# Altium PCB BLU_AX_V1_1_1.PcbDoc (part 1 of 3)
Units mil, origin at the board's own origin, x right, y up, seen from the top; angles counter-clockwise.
Board outline 2623.2 x 4215 mil, 6 copper layers (Top Layer, GND1, PWR, Signal Inner, GND2, Bottom Layer), stack 76.535 mil thick; 238 components, 119 nets, 699 pads, 786 vias.
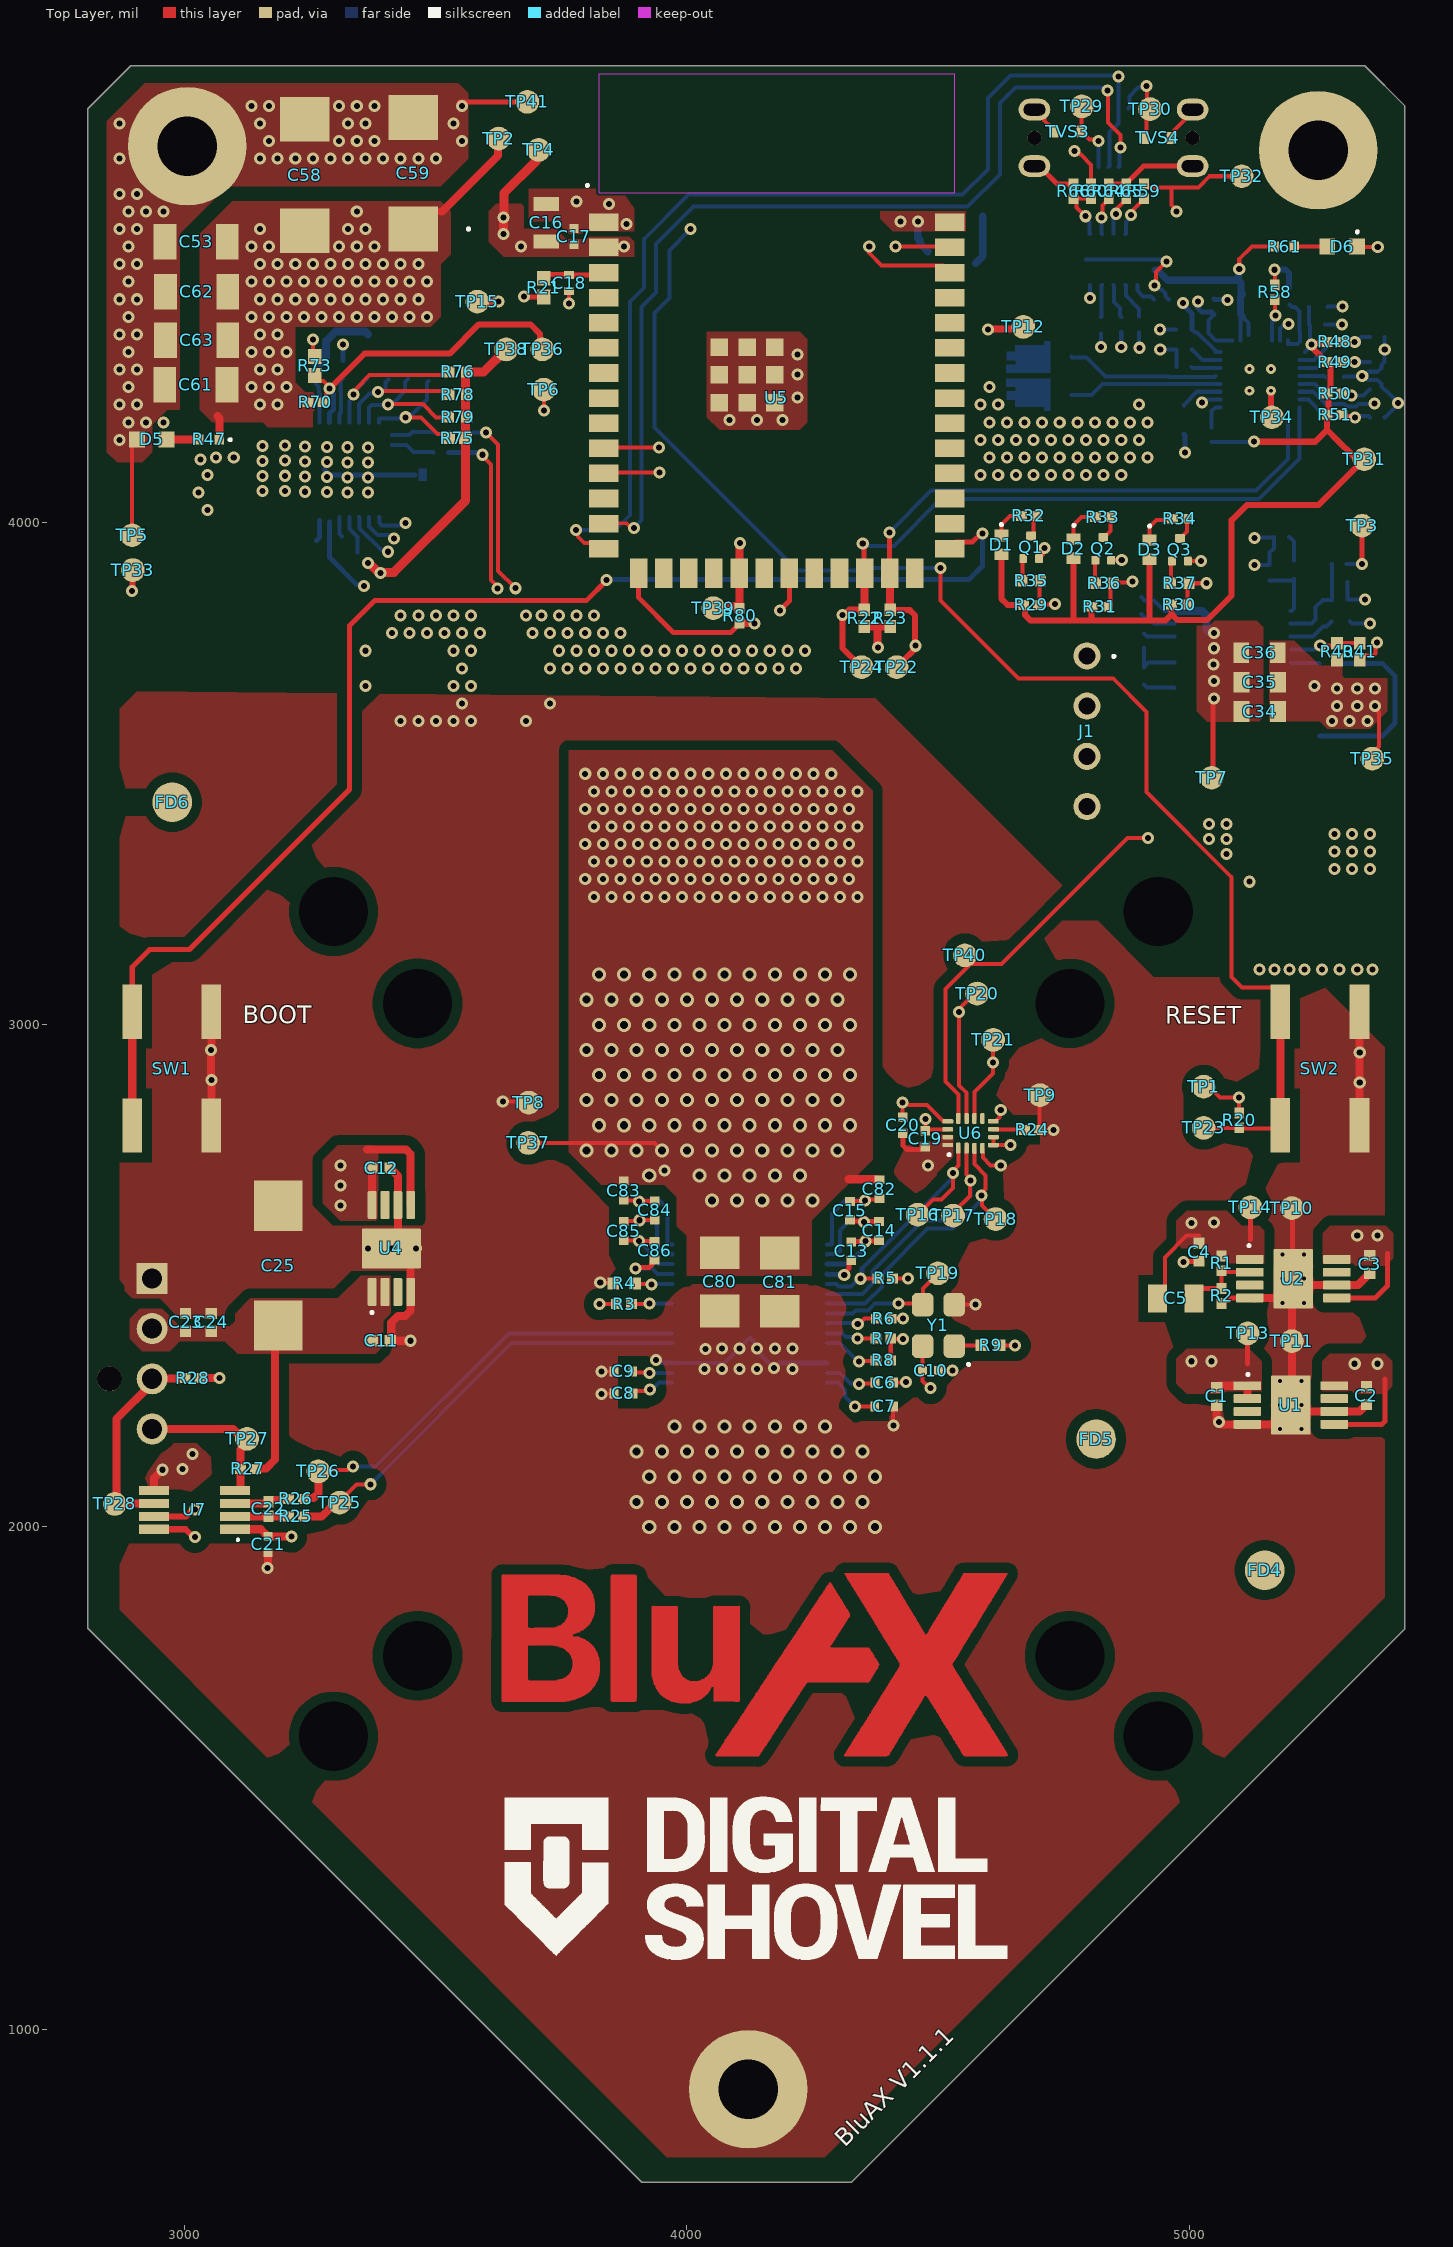
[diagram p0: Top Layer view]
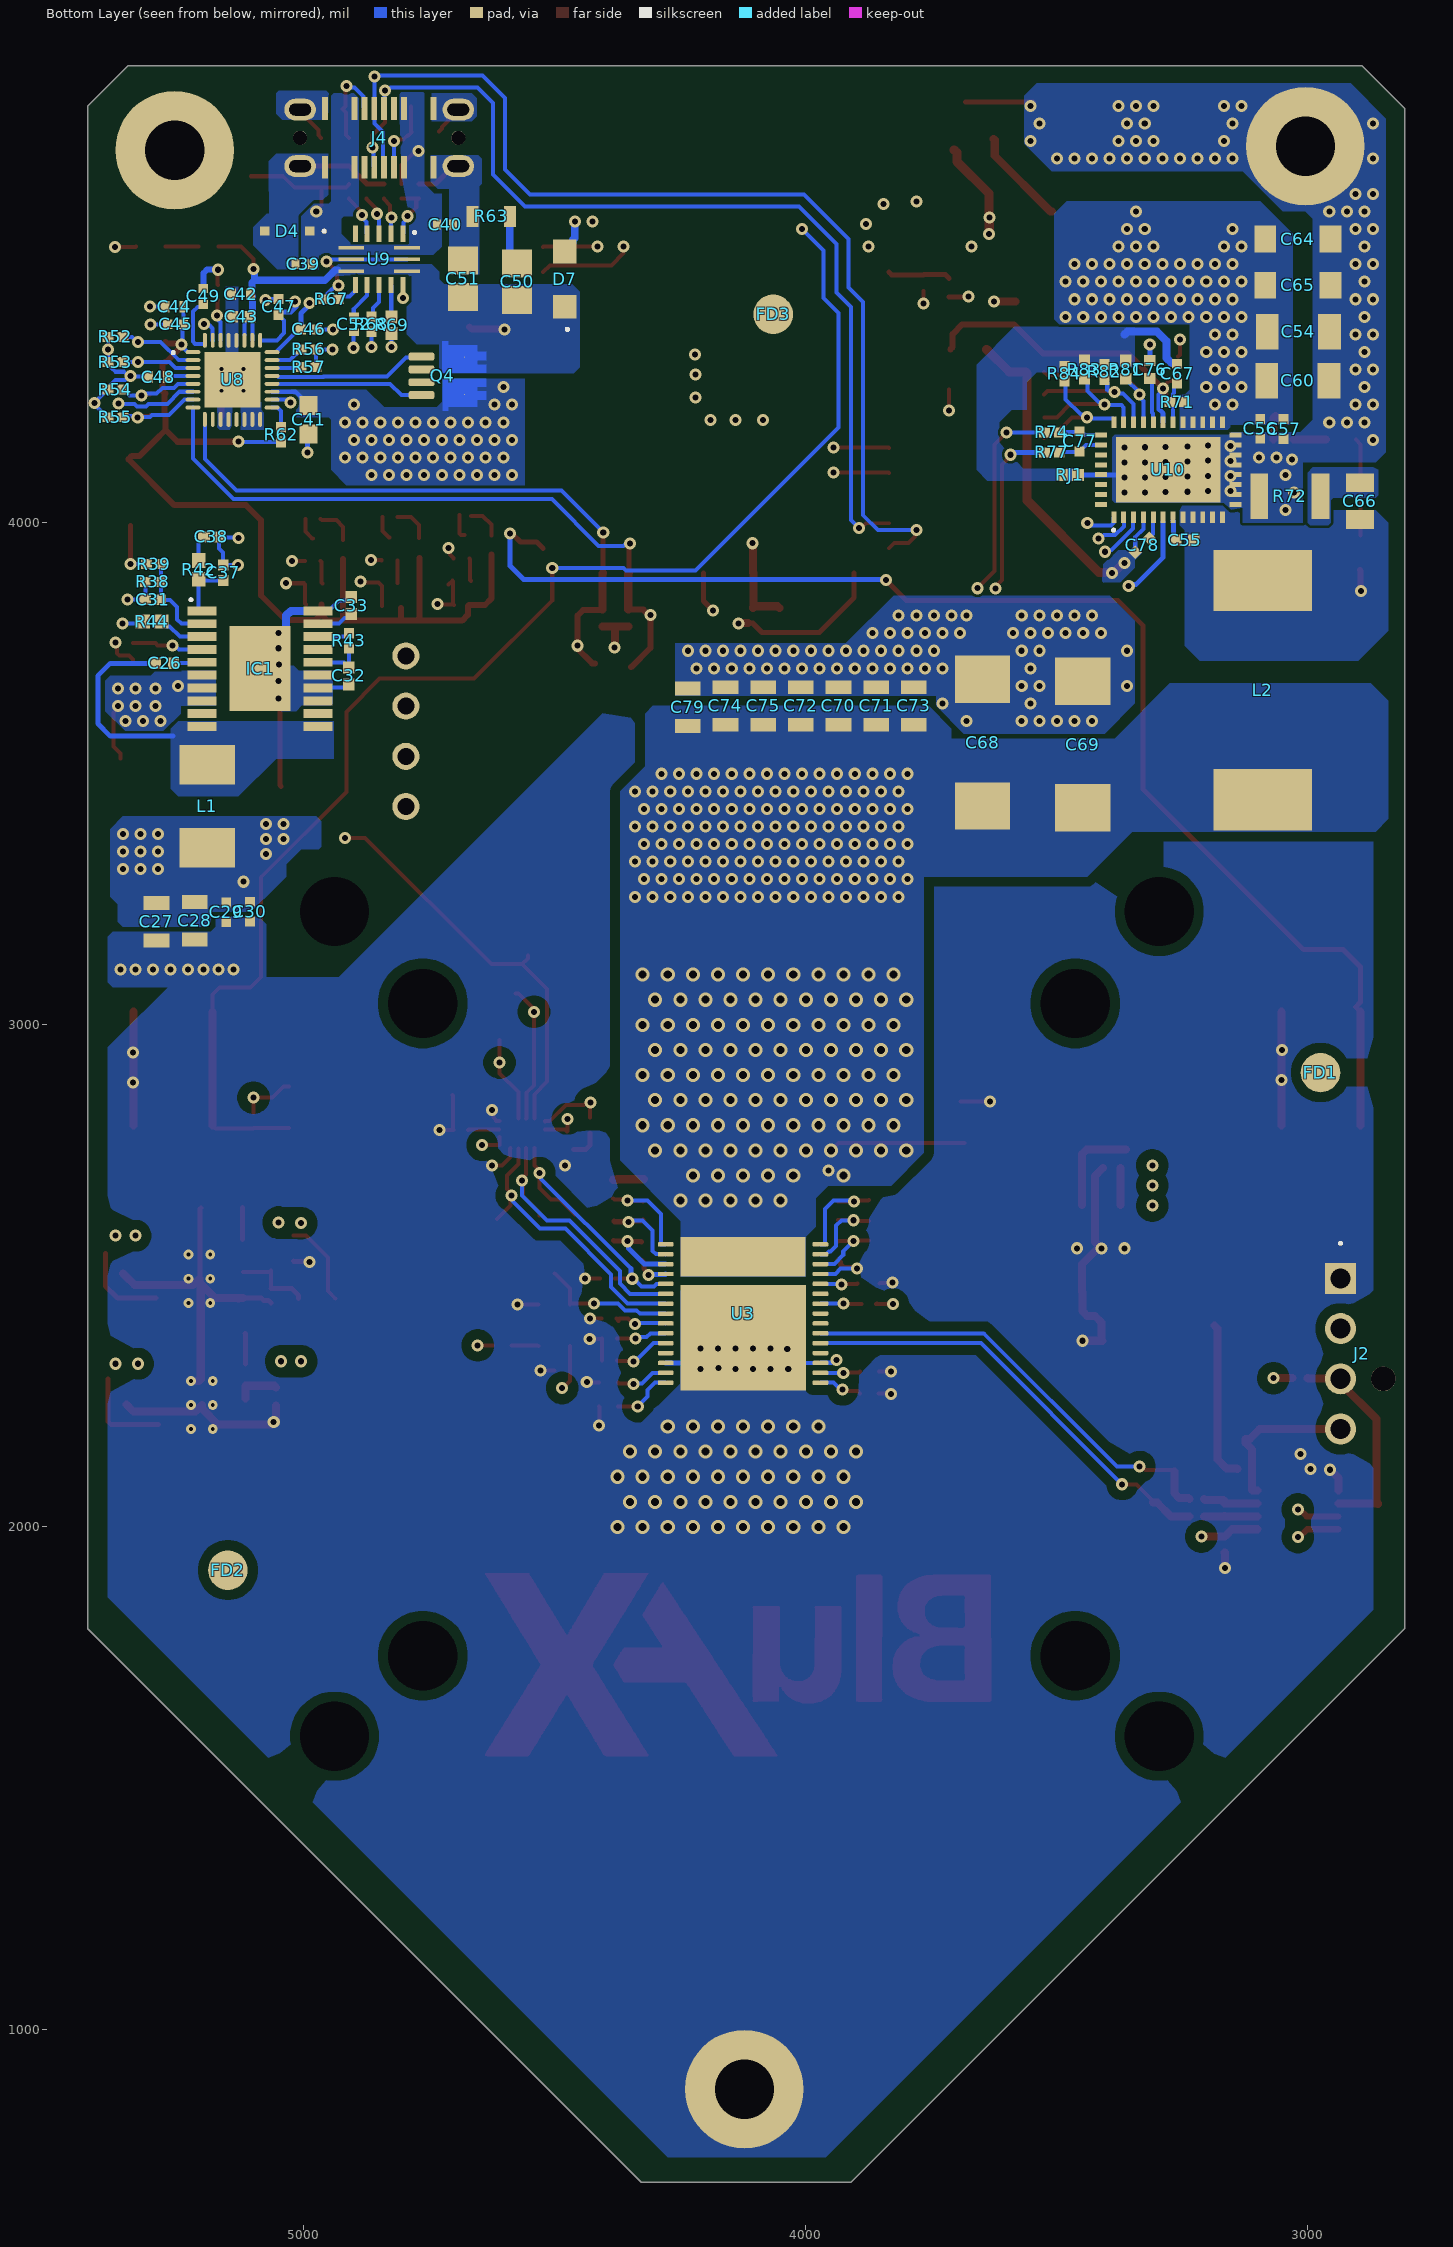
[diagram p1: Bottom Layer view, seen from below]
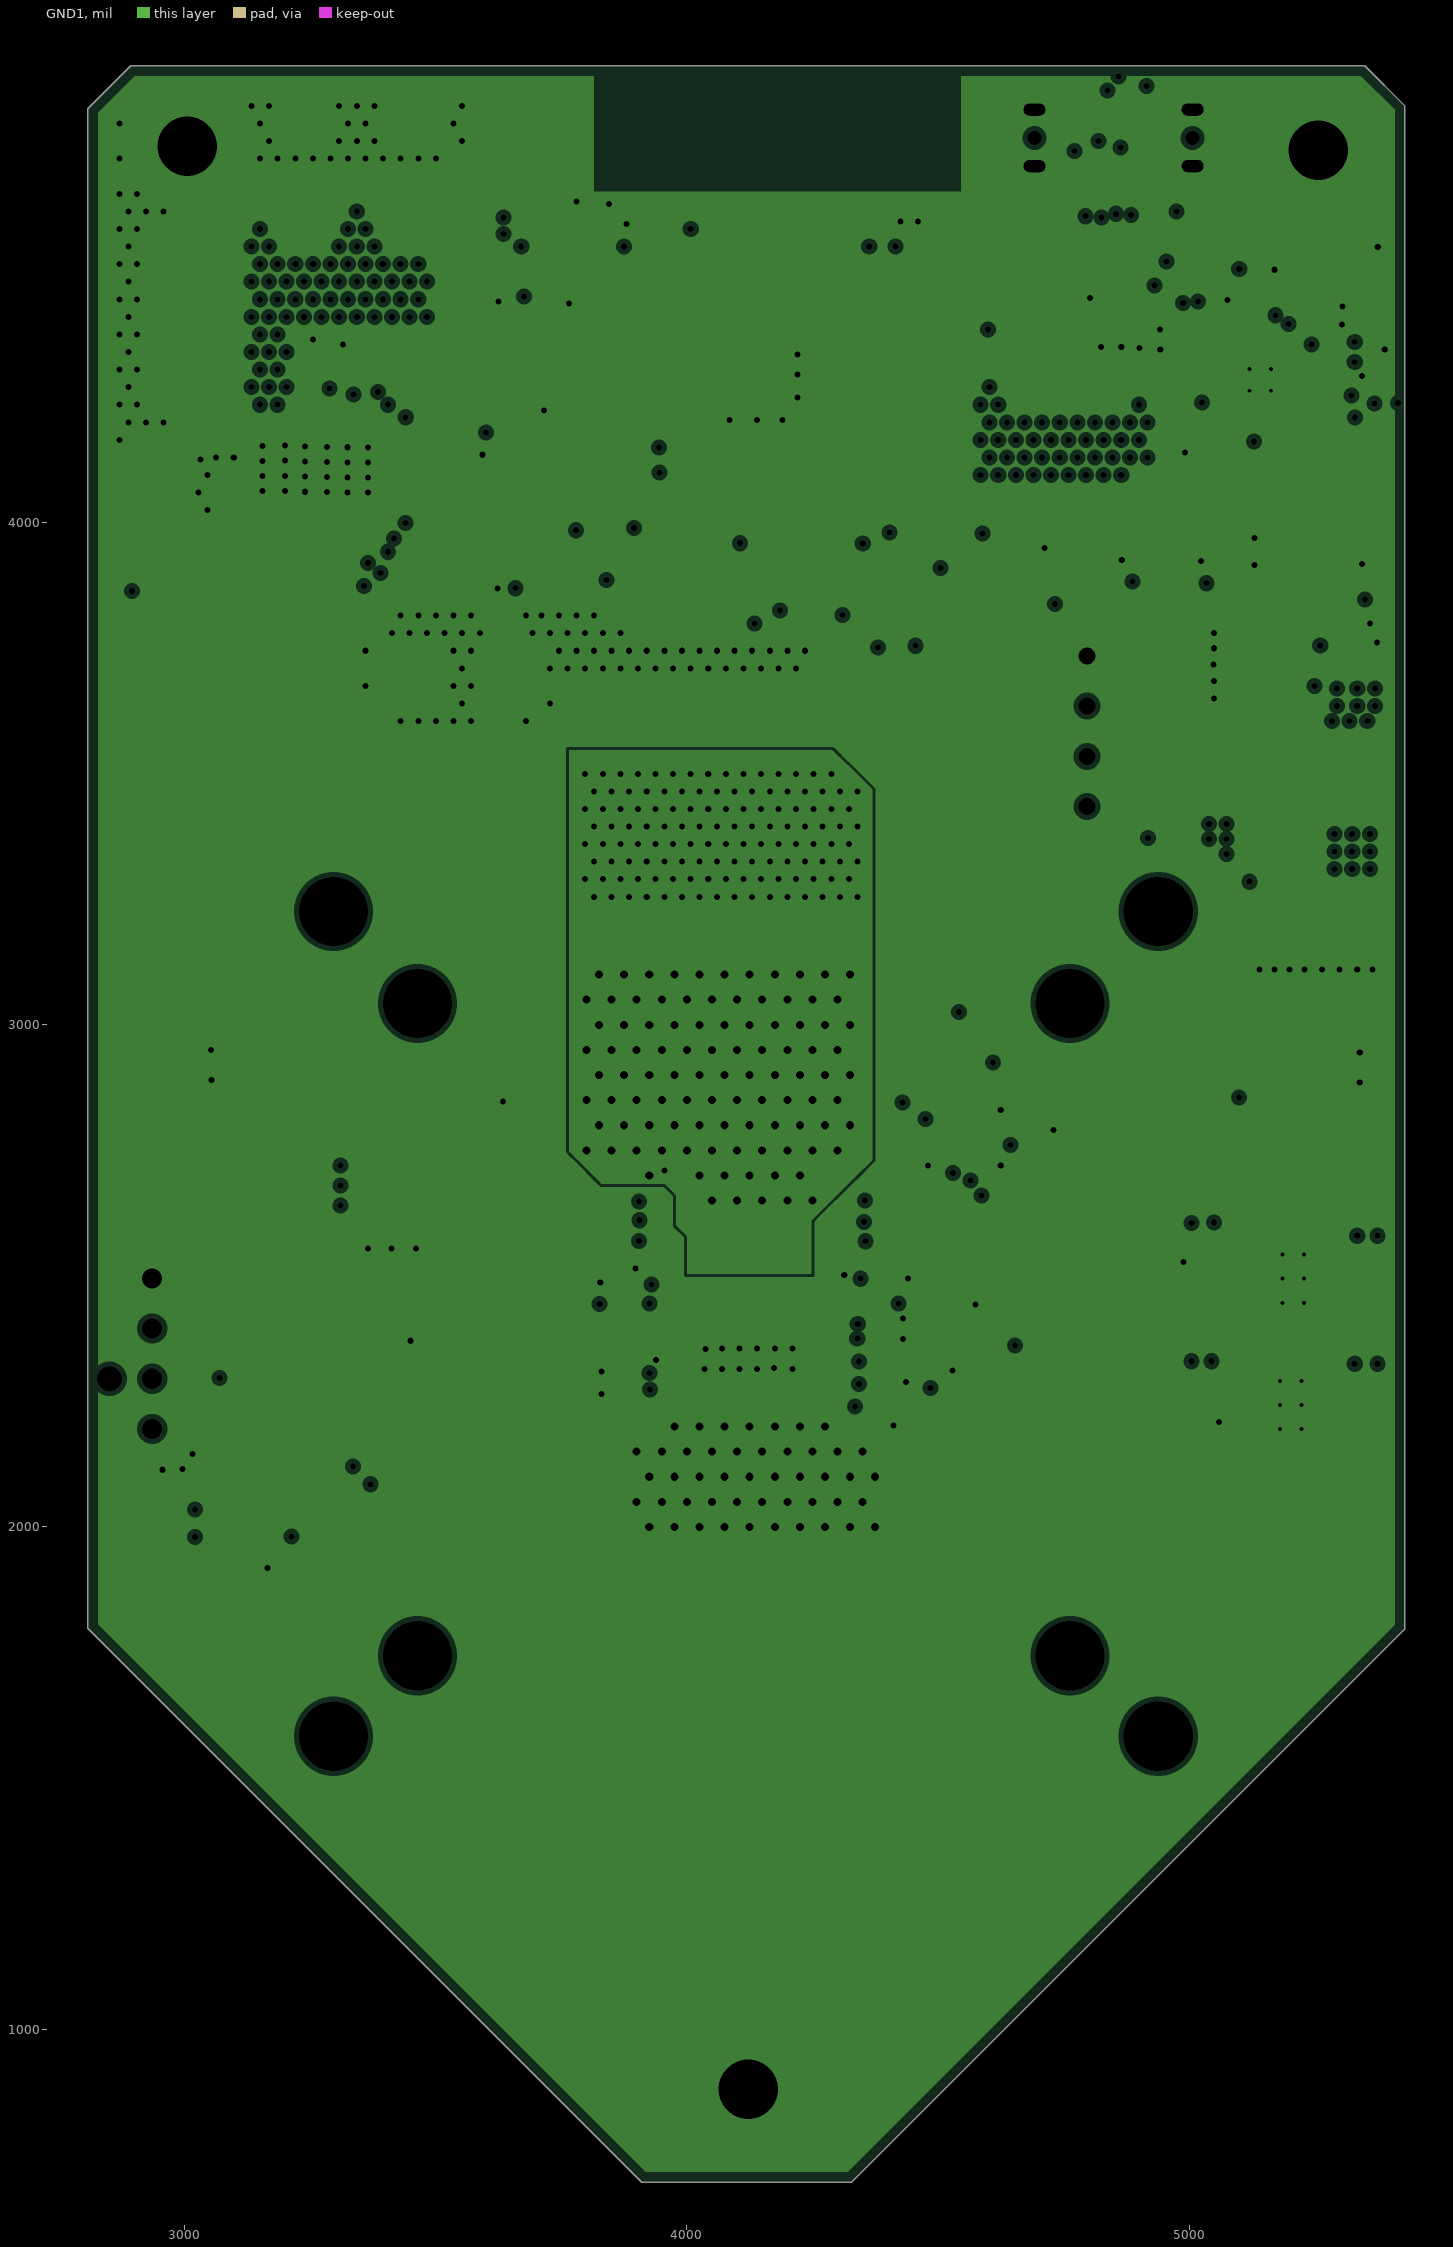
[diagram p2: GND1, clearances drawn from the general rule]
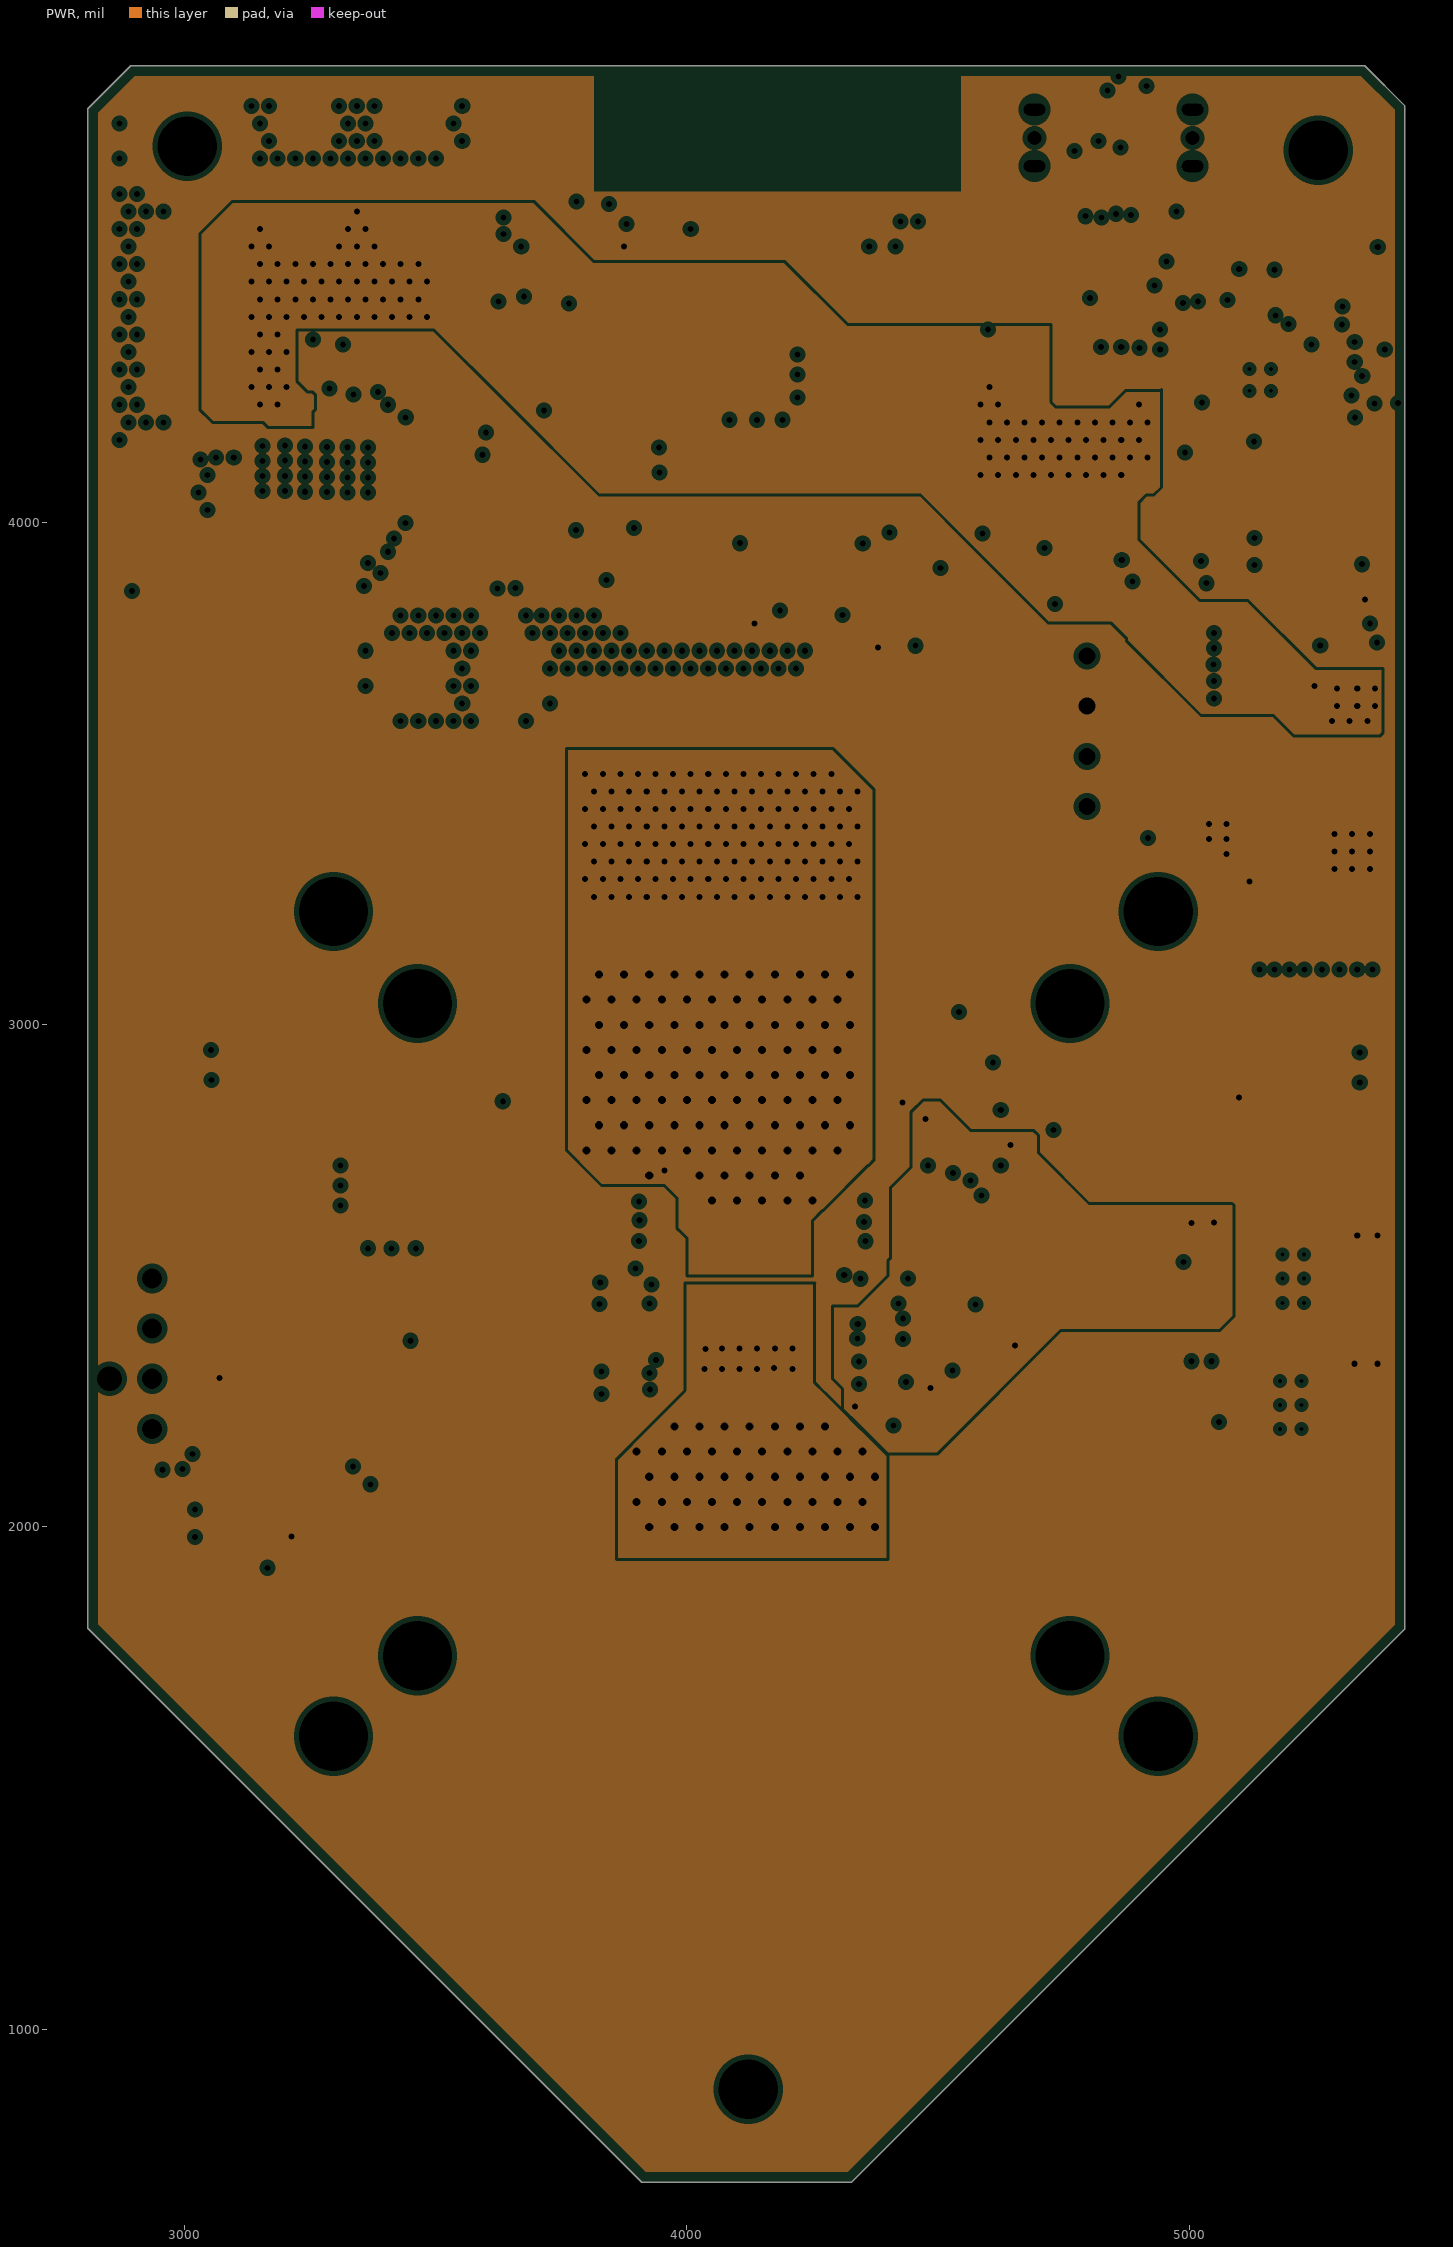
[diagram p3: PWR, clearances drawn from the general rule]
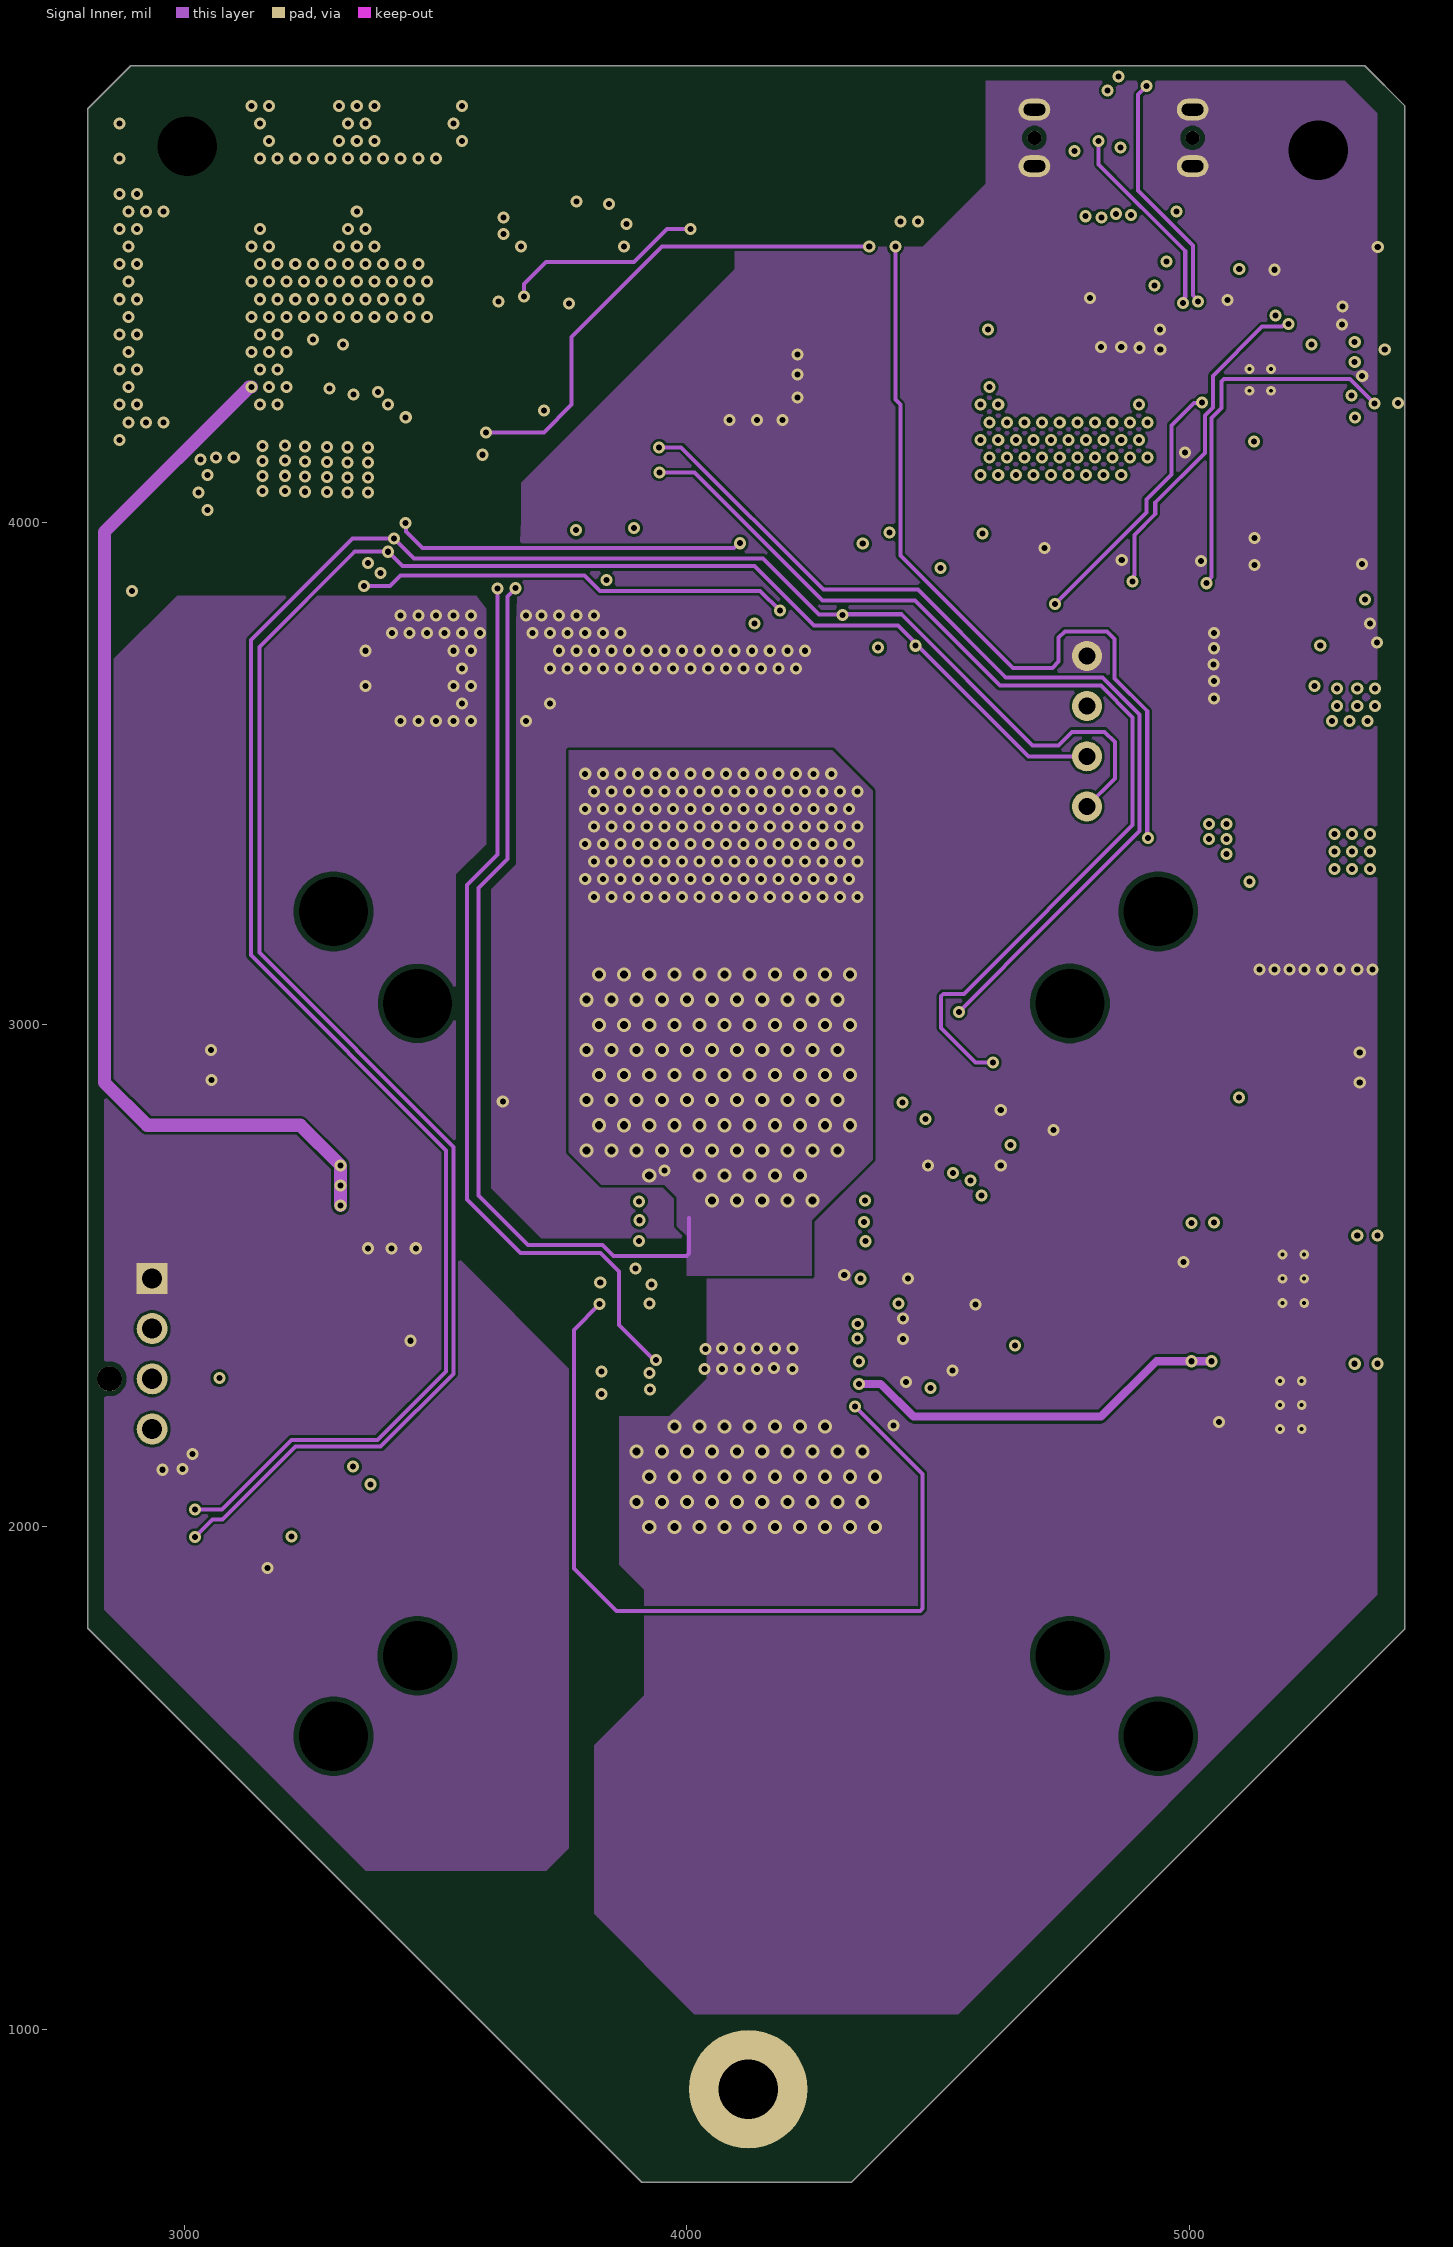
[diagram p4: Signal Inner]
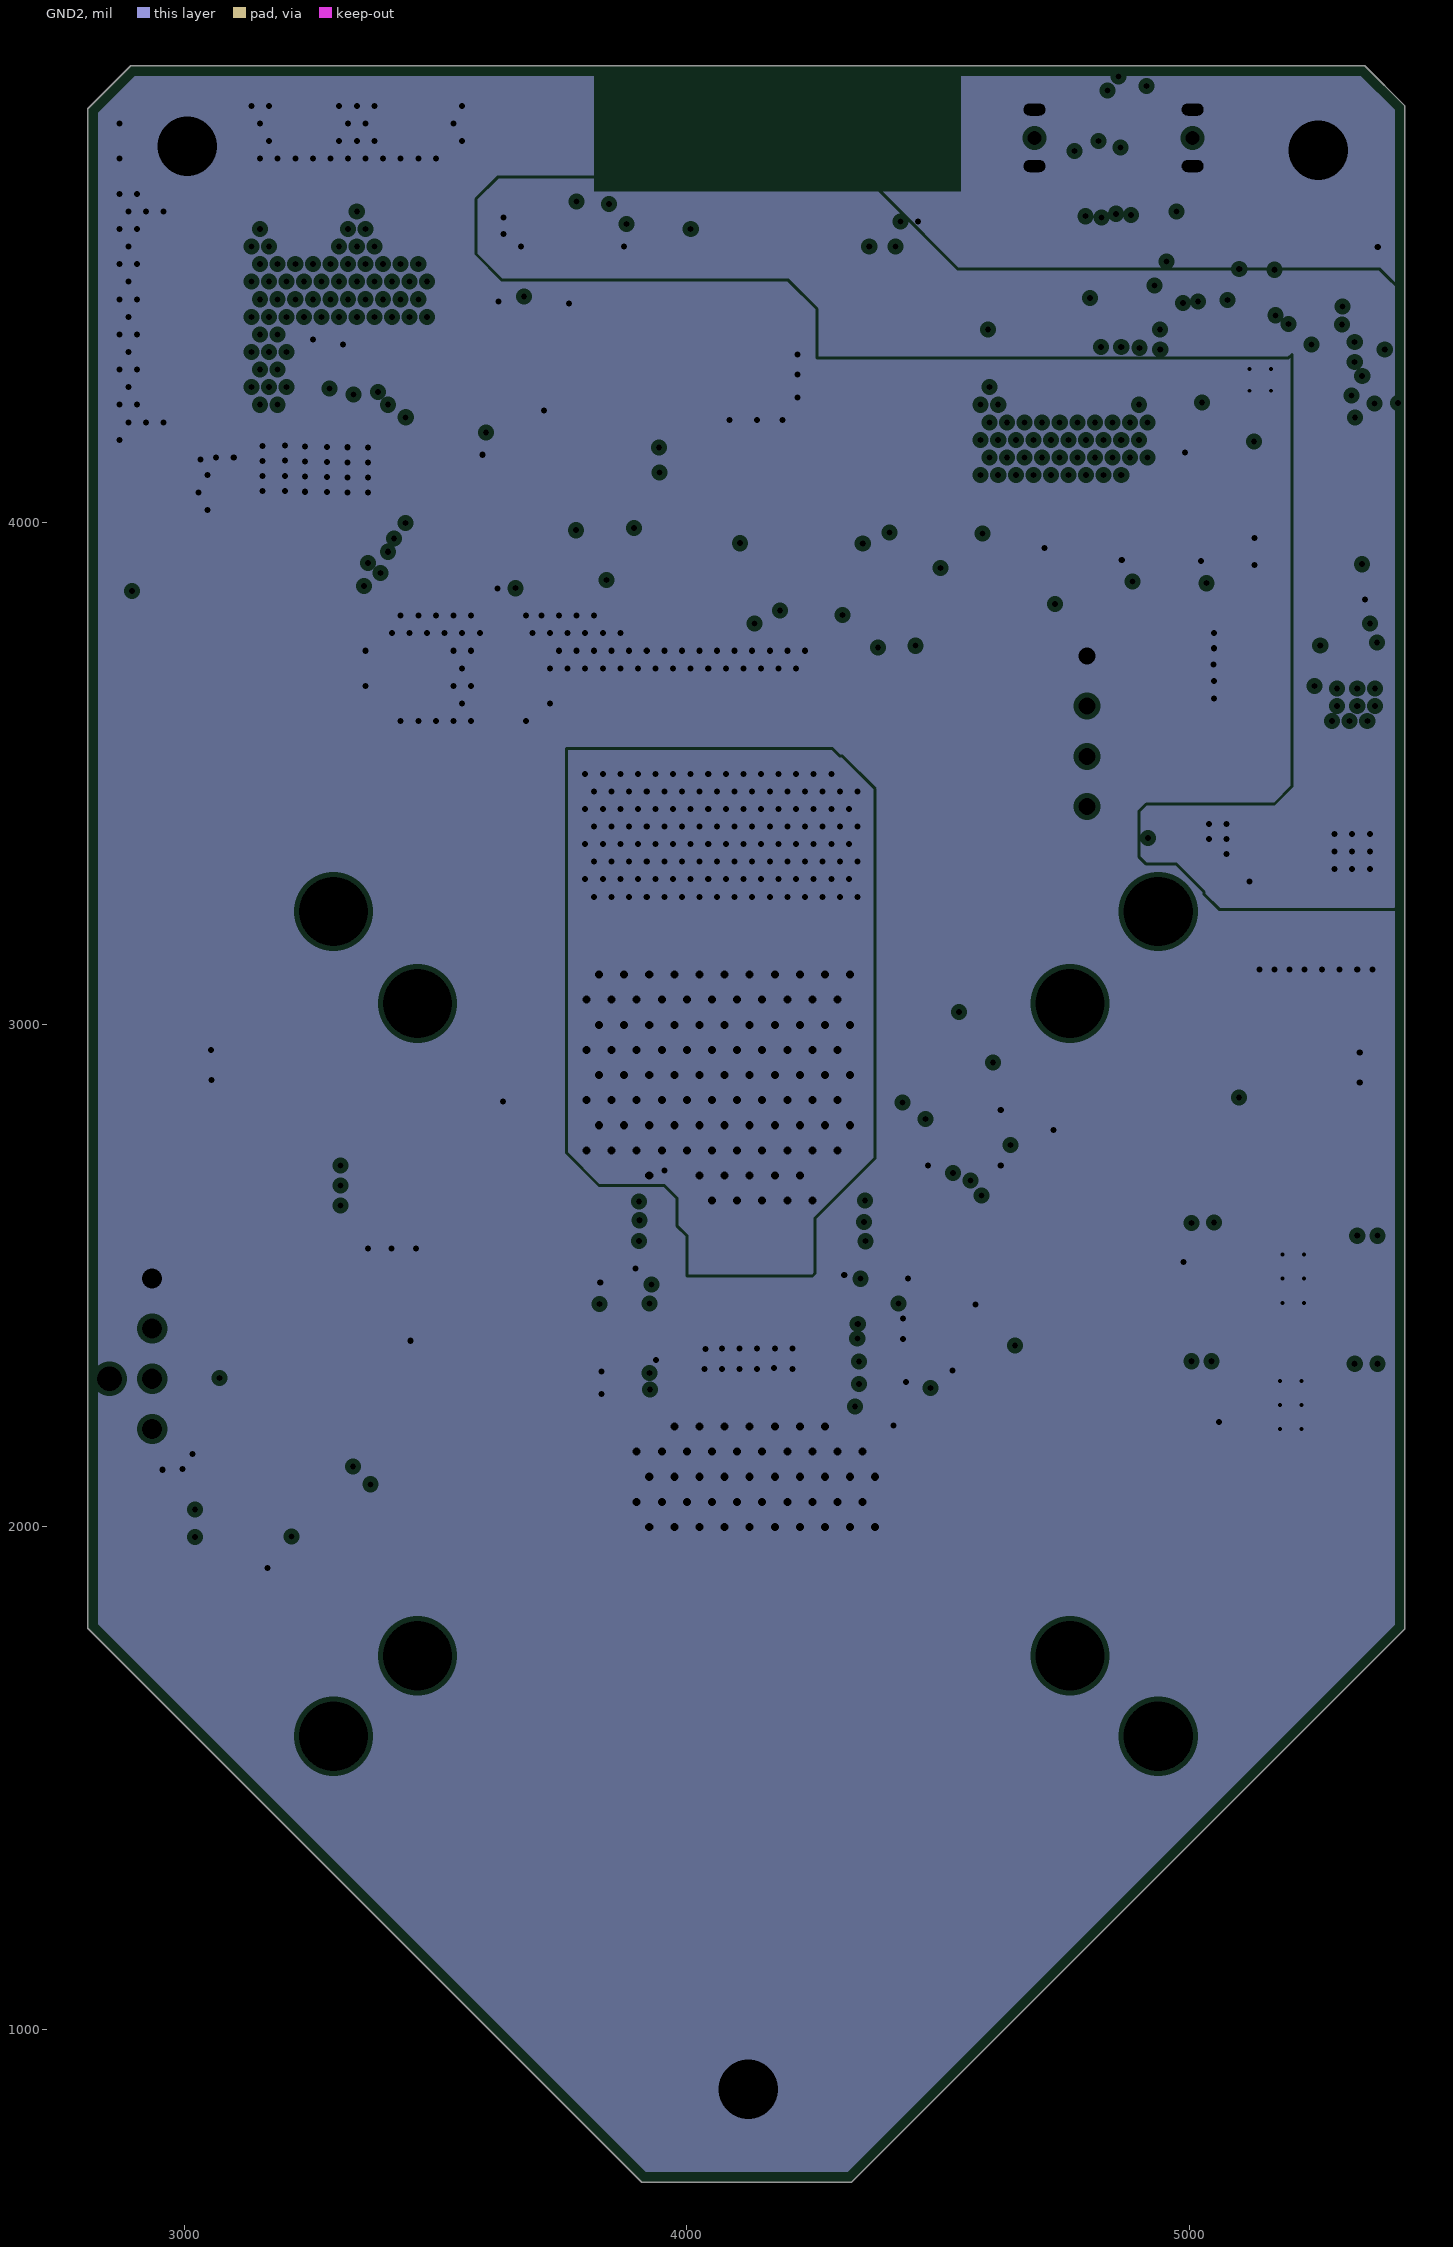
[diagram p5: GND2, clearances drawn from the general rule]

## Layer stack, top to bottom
Top Solder: solder mask 0.4, Solder Resist, Dk 3.5
Top Layer: signal copper 0.689
Dielectric 1: prepreg 4.055, PP-015, Dk 4.45
GND1: plane copper 1.378, net (Multiple Nets)
Dielectric 2: core 28.74, Core-010, Dk 4.6
PWR: plane copper 1.378, net (Multiple Nets)
Dielectric 3: prepreg 4.055, PP-015, Dk 4.45
Signal Inner: signal copper 1.378
Dielectric 4: core 28.74, Core-010, Dk 4.6
GND2: plane copper 1.378, net (Multiple Nets)
Dielectric 5: prepreg 4.055, PP-015, Dk 4.45
Bottom Layer: signal copper 0.689
Bottom Solder: solder mask 0.4, Solder Resist, Dk 3.5

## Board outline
2806.8,1798.2 3910,695 4327.89,695 5430,1797.11 5430,4830 5350,4910 2892.37,4910 2807.63,4825.26 2806.8,4825.26

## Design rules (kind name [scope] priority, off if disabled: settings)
Clearance Clearance_3 [InNamedPolygon('signal pour')] p1: gap=20 ignorepadtopadclearanceinfootprint=FALSE
Clearance Clearance_1 [InNamedPolygon('pour')] p2: gap=20 ignorepadtopadclearanceinfootprint=FALSE
Clearance Clearance_2 [InNamedPolygon('pour')] p3 off: gap=20 ignorepadtopadclearanceinfootprint=FALSE
Clearance [All] p4: gap=5.5 ignorepadtopadclearanceinfootprint=FALSE except(10: Arc-Hole Track-Hole SMDPad-Hole THPad-Hole Via-Hole Fill-Hole Poly-Hole Region-Hole Text-Hole)
DiffPairsRouting [InDifferentialPairClass('USB90_DIFF')] p1: maxlimit=15.88 minlimit=5.5 mostfreqgap=15.88 toplayer_mingap=15.88 toplayer_prefgap=15.88 toplayer_minwidth=7.49 toplayer_maxwidth=7.49 toplayer_prefwidth=7.49 midlayer1_maxgap=5.5 midlayer1_prefgap=5.5 midlayer1_minwidth=8 midlayer1_maxwidth=8 midlayer1_prefwidth=8 bottomlayer_mingap=15.88 bottomlayer_maxgap=15.88 bottomlayer_minwidth=7.94 bottomlayer_maxwidth=7.94 bottomlayer_prefwidth=7.94 impedanceprofiledriven=TRUE impedanceprofileid={67CD1C7F-876C-4BAD-9804-FA39EDEF8C0B} impedanceprofilevalue=90.000000 maxuncoupledlength=500
HoleSize [All] p1: absolutevalues=TRUE maxlimit=500 minlimit=1 maxpercent=80.000 minpercent=20.000
MinimumSolderMaskSliver [All] p1: minsoldermaskwidth=3.5
PlaneClearance [All] p1: clearance=10
PlaneConnect [All] p1: planeconnectstyle=Direct reliefexpansion=20 reliefentries=4 reliefconductorwidth=10 reliefairgap=10
PolygonConnect [All] p1: connectstyle=Direct reliefconductorwidth=10 reliefentries=4 polygonreliefangle="90 Angle" airgapwidth=10
RoutingVias [All] p1: holewidth=28 width=50 viastyle="Through Hole" minholewidth=28 minwidth=50 maxholewidth=28 maxwidth=50
SilkToSolderMaskClearance [IsPad] p1: minsilkscreentomaskgap=3.5 clearancetoexposedcopper=TRUE
SolderMaskExpansion [All] p1: expansion=4 istentingtop=FALSE
Width [All] p1: maxlimit=45 minlimit=8 preferedwidth=10 minimp=50.000000 maximp=50.000000 favimp=50.000000
24 further rules are at their usual default settings.

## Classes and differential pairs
differential pair class USB90_DIFF: USB
component class 14: C11 C12 U4
net class PWR: 1V2 3V3_ESP 3V3_IN DGND FS NetC55_2 SW V_eFuse VBUS VCORE
component class Main: TP3 TP4 TP5 TP6 TP7 TP8 TP9 TP10 TP11 TP15 TP41
component class 13: C6 C7 C8 C9 C13 C14 C15 C80 C81 C82 C83 C84 C85 C86 R3 R4 R5 R6 R7 R8 TP16 TP17 TP18 TP19 U3
component class 12: C21 C22 C23 C24 C25 J2 R25 R26 R27 R28 TP25 TP26 TP27 TP28 U7
component class 11: C1 C2 C3 C4 C5 R1 R2 TP13 TP14 U1 U2
component class 10: J1
component class 9: D1 D2 D3 Q1 Q2 Q3 R29 R30 R31 R32 R33 R34 R35 R36 R37
component class 8: C16 C17 C18 C19 C20 R20 R21 R22 R23 R24 SW1 SW2 TP20 TP21 TP22 TP23 TP24 TP40 U5 U6
component class 7: FD1 FD2 FD3 FD4 FD5 FD6
component class 6: C10 R9 Y1
component class 4: C39 C40 C41 C42 C43 C44 C45 C46 C47 C48 C49 C50 C51 C52 D4 D5 D6 D7 J4 Q4 R47 R48 R49 R50 R51 R52 R53 R54 R55 R56 R57 R58 R59 R60 R61 R62 R63 R64 R65 R66 R67 R68 R69 TP12 TP29 TP30 TP31 TP32 TVS3 TVS4 U8 U9
component class 3: C53 C54 C55 C56 C57 C58 C59 C60 C61 C62 C63 C64 C65 C66 C67 C68 C69 C70 C71 C72 C73 C74 C75 C76 C77 C78 C79 L2 R70 R71 R72 R73 R74 R75 R76 R77 R78 R79 R80 R81 R82 R83 R84 RJ1 TP33 TP34 TP35 TP36 TP37 TP38 TP39 U10
component class 2: C26 C27 C28 C29 C30 C31 C32 C33 C34 C35 C36 C37 C38 IC1 L1 R38 R39 R40 R41 R42 R43 R44 TP1 TP2
differential pair USB: +USB_P -USB_N

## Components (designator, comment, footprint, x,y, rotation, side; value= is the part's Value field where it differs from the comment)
C1 "CC0402KRX7R9BB104" FP-CC0402-IPC_B 5055,2260 r90 top value=100nF
C2 "CC0402KRX7R9BB104" FP-CC0402-IPC_B 5353.31,2261.63 r90 top value=100nF
C3 "CC0402KRX7R9BB104" FP-CC0402-IPC_B 5360,2522.8 r90 top value=100nF
C4 "CC0402KRX7R9BB104" FP-CC0402-IPC_B 5020,2547.2 r90 top value=100nF
C5 "CC0805KRX7R9BB102" FP-CC0805-0_85-MFG 4973.58,2455 r0 top value=1nF
C6 "EMK105BJ105KV-F" FP-0402-L_1_0_0_05-W_0_5-MFG#1 4393.1,2287.63 r0 top value=1uF
C7 "EMK105BJ105KV-F" FP-0402-L_1_0_0_05-W_0_5-MFG#1 4392.72,2240.19 r0 top value=1uF
C8 "EMK105BJ105KV-F" FP-0402-L_1_0_0_05-W_0_5-MFG#1 3873.57,2266.12 r180 top value=1uF
C9 "EMK105BJ105KV-F" FP-0402-L_1_0_0_05-W_0_5-MFG#1 3873.37,2309.84 r180 top value=1uF
C10 "CC0402KRX7R7BB104" FP-CC0402-IPC_C 4485.19,2311.47 r0 top value=0.1uF
C11 "CC0402KRX7R9BB104" FP-CC0402-IPC_B 3391.36,2370.81 r180 top value=100nF
C12 "CC0402KRX7R9BB104" FP-CC0402-IPC_B 3390.79,2714.79 r180 top value=100nF
C13 "EMK105BJ105KV-F" FP-0402-L_1_0_0_05-W_0_5-MFG#2 4327.32,2549.05 r90 top value=1uF
C14 "EMK105BJ105KV-F" FP-0402-L_1_0_0_05-W_0_5-MFG#2 4382.71,2589.42 r90 top value=1uF
C15 "EMK105BJ105KV-F" FP-0402-L_1_0_0_05-W_0_5-MFG#2 4324.57,2629.68 r90 top value=1uF
C16 "GRM21BR61E106KA73L" FP-GRM21B-0_15-MFG 3720,4597.4 r90 top value=10µF
C17 "CC0402KRX7R7BB104" FP-CC0402-IPC_C 3775,4570 r90 top value=0.1uF
C18 "GRM155R71C104KA88D" FP-GRM15-MFG 3765.21,4477.3 r90 top value=100nF
C19 "CC0402KRX7R7BB104" FP-CC0402-IPC_C 4474.73,2773.11 r90 top value=0.1uF
C20 "CC0402KRX7R7BB104" FP-CC0402-IPC_C 4430,2800 r270 top value=0.1uF
C21 "CC0402KRX7R7BB104" FP-CC0402-IPC_C 3165.74,1965.08 r270 top value=0.1uF
C22 "C0402C471K5RACTU" FP-0402-L_1_0_1-W_0_5_0_1-IPC_C 3166.4,2035.94 r270 top value=470pF
C23 "CC0402KRX7R9BB104" FP-CC0402-IPC_B 3001.53,2407.36 r270 top value=100nF
C24 "CC0402KRX7R9BB104" FP-CC0402-IPC_B 3052.65,2407.56 r270 top value=100nF
C25 "293D476X9016D2TE3" VISH-7343-31_N 3186.48,2520.38 r90 top value=47µF
C26 "CC0402KRX7R9BB104" FP-CC0402-IPC_B 5277.2,3720 r180 bottom value=100nF
C27 "GRM21BR71A106KA73L" FP-GRM21B-0_15-MFG 5293.18,3205.35 r270 bottom value=10uF
C28 "GRM21BR71A106KA73L" FP-GRM21B-0_15-MFG 5216.77,3207.15 r270 bottom value=10uF
C29 "CC0402KRX5R6BB105" FP-CC0402-MFG 5154.2,3224 r270 bottom value="1 uF"
C30 "CC0402KRX5R6BB105" FP-CC0402-MFG 5107.2,3225.41 r270 bottom value="1 uF"
C31 "GRM1555C1H221GA01J" CAPC1005X55X25LL05T10 5300.14,3846.72 r0 bottom value=220pF
C32 "GRM155R61E105KA12D" FP-GRM155-0_05-IPC_B 4910,3695 r270 bottom
C33 "GRM155R61E105KA12D" FP-GRM155-0_05-IPC_B 4905,3835 r90 bottom
C34 "C2012X7R1E335K125AB" FP-C2012-125-0_2-MFG 5140.78,3623.97 r180 top value=3.3uF
C35 "C2012X7R1E335K125AB" FP-C2012-125-0_2-MFG 5140.68,3682.23 r180 top value=3.3uF
C36 "C2012X7R1E335K125AB" FP-C2012-125-0_2-MFG 5140.3,3741.03 r180 top value=3.3uF
C37 "GRM1555C1H470GA01D" CAPC1005X55X25LL05T10 5160.4,3900.12 r270 bottom value=47pF
C38 "GRM1555C1H822JE01D" FP-GRM155-0_15-IPC_C 5183.96,3971.62 r180 bottom value=8.2nF
C39 "GRM155R71H223KA12D" FP-GRM155-0_05-MFG 5000.75,4515 r0 bottom value=22nF
C40 "GRM155R71H223KA12D" FP-GRM155-0_05-MFG 4718.4,4593.57 r180 bottom value=22nF
C41 "GCM188R71E105KA64J" FP-GCM188-0_1-IPC_B 4990,4205 r270 bottom value=1uF
C42 "GRM155R61A106ME11D" FP-GRM155-0_2-MFG 5125,4455 r0 bottom value=10uF
C43 "CC0402KRX7R9BB104" FP-CC0402-IPC_B 5124.37,4410.08 r0 bottom value=100nF
C44 "GRM155R61A106ME11D" FP-GRM155-0_2-MFG 5257.54,4430.09 r0 bottom value=10uF
C45 "CC0402KRX7R7BB104" FP-CC0402-IPC_C 5255,4395 r0 bottom value=0.1uF
C46 "C0402C331K5RACTU" FP-C0402-BB-MFG 4990,4385 r180 bottom value=330pF
C47 "C0402C331K5RACTU" FP-C0402-BB-MFG 5050,4430 r90 bottom value=330pF
C48 "GRM155R61A106ME11D" FP-GRM155-0_2-MFG 5290,4290 r0 bottom value=10uF
C49 "CC0402KRX7R7BB104" FP-CC0402-IPC_C 5200,4450.83 r90 bottom value=0.1uF
C50 "GRM21BR61H475KE51L" FP-GRM21B-0_15-IPC_A 4575,4480 r90 bottom value=4.7µF
C51 "GRM21BR61H475KE51L" FP-GRM21B-0_15-IPC_A 4682.79,4485.71 r90 bottom value=4.7µF
C52 "GRM155R71H223KA12D" FP-GRM155-0_05-MFG 4900,4395 r270 bottom value=22nF
C53 "GRM31CC81E226ME11L" FP-GRM31C-0_3-e0_3_0_8-MFG 3022.42,4559.69 r0 top
C54 "GRM31CC81E226ME11L" FP-GRM31C-0_3-e0_3_0_8-MFG 3019.24,4380.2 r0 bottom
C55 "CC0402KRX7R9BB104" FP-CC0402-IPC_B 3245,3965 r180 bottom value=100nF
C56 "CC0402KRX7R8BB222" FP-CC0402-MFG 3094.96,4186.93 r270 bottom value=2.2nF
C57 "CC0402KRX7R8BB222" FP-CC0402-MFG 3048.52,4186.54 r270 bottom value=2.2nF
C58 "593D107X9020E2TE3" 593D107X9020E2TE3-Footprint-1 3237.67,4694.89 r180 top
C59 "593D107X9020E2TE3" 593D107X9020E2TE3-Footprint-1 3453.81,4698.65 r180 top
C60 "GRM31CC81E226ME11L" FP-GRM31C-0_3-e0_3_0_8-MFG 3019.85,4282.63 r0 bottom
C61 "GRM31CC81E226ME11L" FP-GRM31C-0_3-e0_3_0_8-MFG 3022.01,4275 r0 top
C62 "GRM31CC81E226ME11L" FP-GRM31C-0_3-e0_3_0_8-MFG 3023.73,4459.68 r0 top
C63 "GRM31CC81E226ME11L" FP-GRM31C-0_3-e0_3_0_8-MFG 3023.6,4362.99 r0 top
C64 "C3216X5R1E476M160AC" FP-C3216-160-0_2-MFG 3020,4565 r180 bottom
C65 "C3216X5R1E476M160AC" FP-C3216-160-0_2-MFG 3020.09,4472.72 r180 bottom
C66 "CC0805KRX7R9BB102" FP-CC0805-0_85-MFG 2896.43,4042.96 r90 bottom value=1nF
C67 "CC0402KRX5R6BB105" FP-CC0402-MFG 3260.5,4297.02 r90 bottom value="1 uF"
C68 "EEF-SX0J181ER" EEF-SX0J181ER-Footprint-1 3646.83,3559.35 r90 bottom value="180 uF"
C69 "EEF-SX0J181ER" EEF-SX0J181ER-Footprint-1 3447.15,3555.53 r90 bottom value="180 uF"
C70 "GRM21BZ70J226ME44L" FP-GRM21B-0_2-e0_2_0_7-MFG 3935,3635 r90 bottom value=22uF
C71 "GRM21BZ70J226ME44L" FP-GRM21B-0_2-e0_2_0_7-MFG 3860,3635 r90 bottom value=22uF
C72 "GRM21BZ70J226ME44L" FP-GRM21B-0_2-e0_2_0_7-MFG 4010,3635 r90 bottom value=22uF
C73 "GRM21BR71A106KA73L" FP-GRM21B-0_15-MFG 3785,3635 r90 bottom value=10uF
C74 "GRM21BR71A106KA73L" FP-GRM21B-0_15-MFG 4160,3635 r90 bottom value=10uF
C75 "GRM21BR71A106KA73L" FP-GRM21B-0_15-MFG 4085,3635 r90 bottom value=10uF
C76 "CC0402KRX7R9BB104" FP-CC0402-IPC_B 3315,4305 r90 bottom value=100nF
C77 "CC0402KRX7R9BB101" FP-CC0402-MFG 3454.68,4161.81 r270 bottom value=100pF
C78 "CC0402KRX5R6BB105" FP-CC0402-MFG 3330,3955 r315 bottom value="1 uF"
C79 "GRM21BZ70J226ME44L" FP-GRM21B-0_2-e0_2_0_7-MFG 4235,3632.6 r90 bottom value=22uF
C80 "GRM31CR60J107MEA8K" FP-GRM31C-0_3-e0_3_0_8-IPC_A 4065.03,2488.27 r90 top
C81 "GRM31CR60J107MEA8K" FP-GRM31C-0_3-e0_3_0_8-IPC_A 4184.74,2487.41 r90 top
C82 "EMK105BJ105KV-F" FP-0402-L_1_0_0_05-W_0_5-MFG#2 4383.52,2672.81 r90 top value=1uF
C83 "EMK105BJ105KV-F" FP-0402-L_1_0_0_05-W_0_5-MFG#2 3874.3,2670.02 r270 top value=1uF
C84 "EMK105BJ105KV-F" FP-0402-L_1_0_0_05-W_0_5-MFG#2 3935.91,2630.37 r270 top value=1uF
C85 "EMK105BJ105KV-F" FP-0402-L_1_0_0_05-W_0_5-MFG#2 3874.26,2589.32 r270 top value=1uF
C86 "EMK105BJ105KV-F" FP-0402-L_1_0_0_05-W_0_5-MFG#2 3935.67,2550.01 r270 top value=1uF
D1 "VLMS1500-GS08" FP-VLMO1500-GS08-MFG 4626.25,3955.82 r270 top value=Red
D2 "VLMG1500-GS08" FP-VLMO1500-GS08-MFG 4769.76,3948.4 r270 top value=Green
D3 "VLMY1500-GS08" FP-VLMO1500-GS08-MFG 4921.42,3946.5 r270 top value=Yellow
D4 "SP4024-01FTG-C" FP-SP4024-CA-MFG 5032.73,4580.91 r0 bottom value=24V
D5 "LB Q39E-N1OO-35-1" FP-LB_Q39E-MFG 2934.08,4165.75 r0 top
D6 "LB Q39E-N1OO-35-1" FP-LB_Q39E-MFG 5304.74,4550.04 r180 top
D7 "PMEG4030ER,115" FP-SOD123W-MFG 4480,4485 r90 bottom value=3A
FD1 "FID1X2R" FID1X2R#1 2975,2905 r180 bottom
FD2 "FID1X2R" FID1X2R#1 5150.87,1913.96 r180 bottom
FD3 "FID1X2R" FID1X2R#1 4065,4415 r180 bottom
FD4 "FID1X2R" FID1X2R#1 5150.87,1913.96 r0 top
FD5 "FID1X2R" FID1X2R#2 4815,2175 r0 top
FD6 "FID1X2R" FID1X2R#1 2975,3443.33 r0 top
IC1 "MP4570GF-Z" MP4570GF-Z-Footprint-1 5086.86,3709.27 r180 bottom
J1 "76341-304LF" 76341-304LF-Footprint-1 4773.56,3606.37 r270 top
J2 "47053-1000" FP-470531000-MFG 2949.96,2345 r90 bottom
J4 "USB4145-03-0170-C_REVA2" GCT_USB4145-03-0170-C_REVA2 4849.62,4766.5 r0 bottom
L1 "SRP5020TA-6R8M" SRP5020TA-6R8M-Footprint-1 5195,3435.04 r270 bottom value=6.8uH
L2 "SRP1265A-R33M" SRP1265A-R33M 3085,3666.5 r270 bottom
Q1 "RUM002N05T2L" ROHM-SOT723-3_V 4685.5,3951.15 r90 top
Q2 "RUM002N05T2L" ROHM-SOT723-3_V 4829.2,3947.79 r90 top
Q3 "RUM002N05T2L" ROHM-SOT723-3_V 4981.99,3946.3 r90 top
Q4 "SISF00DN-T1-GE3" "New footprint 1" 4765.45,4254.13 r180 bottom value=30V
R1 "RK73H1ETTP5112F" RESC1005X40X25LL10T10 5065,2525 r90 top value=51.1kR
R2 "RK73H1ETTP1023F" RESC1005X40X25LL10T10 5065,2460 r90 top value=102kR
R3 "RK73H1ETTP1001F" RESC1005X40X25LL10T10 3874.77,2443.7 r180 top value=1kR
R4 "RK73H1ETTP2201F" RK73H1ETTP2201F-Footprint-1 3875,2485 r0 top value=2.2kΩ
R5 "RK73H1ETTP1002F" RESC1005X40X25LL10T10 4395,2495 r180 top value=10kR
R6 "RK73H1ETTP1002F" RESC1005X40X25LL10T10 4392.25,2414.73 r180 top value=10kR
R7 "RK73H1ETTP1001F" RESC1005X40X25LL10T10 4391.18,2375.01 r180 top value=1kR
R8 "RK73H1ETTP1001F" RESC1005X40X25LL10T10 4391.18,2331.64 r180 top value=1kR
R9 "RK73Z1ETTP" FP-RK73Z1E-IPC_B 4604.71,2361.58 r0 top value=Jumper
R20 "RK73H1ETTP1002F" RESC1005X40X25LL10T10 5100,2809.76 r90 top value=10kR
R21 "RK73H1ETTP3300F" RESC1005X40X25ML10T10 3714.79,4468.1 r270 top value=330R
R22 "RK73H1ETTP2201F" RESC1005X40X25NL10T10 4353.31,3810 r270 top value=2.2kR
R23 "RK73H1ETTP2201F" RESC1005X40X25NL10T10 4405,3810 r270 top value=2.2kR
R24 "RK73B1ETTP103J" RESC1005X40X25LL10T10 4687.32,2790.82 r0 top value=10kΩ
R25 "RK73H1ETTP1000F" RESC1005X40X25LL10T10 3221.4,2020.94 r180 top value=100R
R26 "RK73H1ETTP1000F" RESC1005X40X25LL10T10 3221.4,2055.94 r180 top value=100R
R27 "RK73B1ETTP103J" RESC1005X40X25LL10T10 3125.72,2115.68 r0 top value=10kΩ
R28 "RK73H1ETTP5601F" RESC1005X40X25LL10T10 3015.77,2296.27 r0 top value=5.6kR
R29 "RK73H1ETTP1002F" RESC1005X40X25LL10T10 4685.5,3836.15 r0 top value=10kR
R30 "RK73H1ETTP1002F" RESC1005X40X25LL10T10 4980.21,3836.8 r0 top value=10kR
R31 "RK73H1ETTP1002F" RESC1005X40X25LL10T10 4821.75,3832.61 r0 top value=10kR
R32 "RK73H1ETTP2322F" RESC1005X40X25LL10T10 4681.06,4013.57 r180 top value=23.2kΩ
R33 "RK73H1ETTP2322F" RESC1005X40X25LL10T10 4828.35,4011.27 r180 top value=23.2kΩ
R34 "RK73H1ETTP2322F" RESC1005X40X25LL10T10 4981.58,4007.82 r180 top value=23.2kΩ
R35 "RK73Z1ETTP" FP-RK73Z1E-IPC_B 4685.43,3884.43 r180 top value=0R
R36 "RK73Z1ETTP" FP-RK73Z1E-IPC_B 4831.16,3879.73 r180 top value=0R
R37 "RK73Z1ETTP" FP-RK73Z1E-IPC_B 4981.14,3879.4 r180 top value=0R
R38 "RK73H1ETTP1002F" RESC1005X40X25LL10T10 5300.77,3882.04 r0 bottom value=10kR
R39 "RK73H1ETTP4321F" RESC1005X40X25LL10T10 5298.65,3917.71 r180 bottom value=4.32kR
R40 "RK73H1ETTP1003F" RESC1005X40X25NL10T10 5295,3743.27 r270 top value=100kR
R41 "RK73H1ETTP6982F" RESC1005X40X25NL10T10 5340,3743.27 r90 top value=69.8kR
R42 "RK73H1ETTP2551F" RESC1005X40X25ML10T10 5209.09,3906.13 r270 bottom value=2.55kR
R43 "RK73H1ETTP1003F" RESC1005X40X25LL10T10 4910,3765 r270 bottom value=100kR
R44 "RK73H1ETTP1023F" RESC1005X40X25ML10T10 5302.33,3803.1 r180 bottom value=102kR
R47 "ERA-2AEB102X" FP-ERA2A-MFG 3048.52,4165.75 r0 top value=1kR
R48 "RK73H1ETTP1003F" RESC1005X40X25LL10T10 5290,4360 r180 top value=100kR
R49 "RK73H1ETTP1003F" RESC1005X40X25LL10T10 5290,4320 r180 top value=100kR
R50 "RK73H1ETTP1003F" RESC1005X40X25LL10T10 5289.73,4257.03 r180 top value=100kR
R51 "RK73H1ETTP1003F" RESC1005X40X25LL10T10 5290,4215 r180 top value=100kR
R52 "RK73H1ETTP4991F" RESC1005X40X25LL10T10 5375,4370 r180 bottom value=4.99kR
R53 "RK73H1ETTP1183F" RESC1005X40X25LL10T10 5375,4320 r180 bottom value=118kR
R54 "RK73H1ETTP2322F" RESC1005X40X25LL10T10 5375,4265 r180 bottom value=23.2kΩ
R55 "RK73H1ETTP4991F" RESC1005X40X25LL10T10 5375,4210 r180 bottom value=4.99kR
R56 "RK73B1ETTP103J" RESC1005X40X25LL10T10 4990,4345 r0 bottom value=10kΩ
R57 "RK73B1ETTP103J" RESC1005X40X25LL10T10 4990,4310 r0 bottom value=10kΩ
R58 "RK73B1ETTP103J" RESC1005X40X25LL10T10 5170.61,4458.78 r270 top value=10kΩ
R59 "RK73H1ETTP1003F" RESC1005X40X25LL10T10 4910,4660 r90 top value=100kR
R60 "RK73H1ETTP1003F" RESC1005X40X25LL10T10 4805,4660 r90 top value=100kR
R61 "ERA-2AEB102X" FP-ERA2A-MFG 5189.74,4550.04 r180 top value=1kR
R62 "RK73B1ETTP103J" RESC1005X40X25LL10T10 5045,4175.24 r270 bottom value=10kΩ
R63 "RK73H2ATTD3R60F" FP-RK73H2A-MFG 4626.64,4610.05 r180 bottom value=3.6R
R64 "RK73H1ETTP1003F" RESC1005X40X25LL10T10 4840,4660 r270 top value=100kR
R65 "RK73H1ETTP1003F" RESC1005X40X25LL10T10 4875,4660 r270 top value=100kR
R66 "RK73H1ETTP1003F" RESC1005X40X25LL10T10 4770,4660 r270 top value=100kR
R67 "RK73B1ETTP103J" RESC1005X40X25LL10T10 4945,4445 r180 bottom value=10kΩ
R68 "RK73H1ETTP5601F" RESC1005X40X25LL10T10 4865,4395 r90 bottom value=5.6kR
R69 "RK73H1ETTP1303F" RESC1005X40X25NL10T10 4825,4393.27 r90 bottom value=130kR
R70 "RK73H1ETTP2552F" RESC1005X40X25LL10T10 3260,4240 r180 top value=25.5kR
R71 "RK73H1ETTP10R0F" RESC1005X40X25LL10T10 3260.28,4240.13 r180 bottom value=10R
R72 "RK73H2ETTD1R00F" FP-RK73H2E-MFG 3035.93,4052.98 r180 bottom value=1R
R73 "RK73H1ETTP4321F" RESC1005X40X25ML10T10 3258.68,4312.11 r270 top value=4.32kR
R74 "RK73H1ETTP49R9F" RESC1005X40X25LL10T10 3509.76,4180 r0 bottom value=49.9R
R75 "RK73H1ETTP8251F" RESC1005X40X25NL10T10 3542.52,4168.52 r180 top value=8.25kR
R76 "RK73Z1ETTP" FP-RK73Z1E-IPC_B 3543.62,4300.25 r0 top value=0R
R77 "RK73H1ETTP49R9F" RESC1005X40X25LL10T10 3510,4140 r0 bottom value=49.9R
R78 "RK73Z1ETTP" FP-RK73Z1E-IPC_B 3543.62,4255.25 r0 top value=0R
R79 "RK73Z1ETTP" FP-RK73Z1E-IPC_B 3543.11,4210.48 r0 top value=0R
R80 "RK73H1ETTP1002F" RESC1005X40X25LL10T10 4105,3815 r270 top value=10kR
R81 "RK73Z1ETTP" FP-RK73Z1E-IPC_B 3362.97,4304.78 r270 bottom value=0R
R82 "RK73H1ETTP6812F" RESC1005X40X25LL10T10 3405.52,4300.3 r270 bottom value=68.1kR
R83 "RK73Z1ETTP" FP-RK73Z1E-IPC_B 3445,4305 r270 bottom value=0R
R84 "RK73H1ETTP1472F" RESC1005X40X25LL10T10 3485.17,4296.6 r270 bottom value=14.7kR
RJ1 "Net Tie 12x8mil" SHORT06-FP 3473.89,4095.24 r180 bottom net-tie
SW1 "B3SL-1005P" SW_B3SL-1002P_OMR 2974.09,2912.83 r90 top
SW2 "B3SL-1005P" SW_B3SL-1002P_OMR 5260.55,2912.84 r90 top
TP1 "TP" TP-Footprint-1 5029.17,2876.87 r90 top
TP2 "TP" TP-Footprint-1 3625,4765 r0 top
TP3 "TP" TP-Footprint-1 5344.69,3994 r0 top
TP4 "TP" TP-Footprint-1 3704.6,4742.5 r0 top
TP5 "TP" TP-Footprint-1 2895,3975 r0 top
TP6 "TP" TP-Footprint-1 3715,4265 r0 top
TP7 "TP" TP-Footprint-1 5045,3492.07 r0 top
TP8 "TP" TP-Footprint-1 3685,2845 r0 top
TP9 "TP" TP-Footprint-1 4703.22,2860.02 r0 top
TP10 "TP" TP-Footprint-1 5205,2635 r0 top
TP11 "TP" TP-Footprint-1 5205,2370 r0 top
TP12 "TP" TP-Footprint-1 4670,4390 r0 top
TP13 "TP" TP-Footprint-1 5116.67,2385.49 r0 top
TP14 "TP" TP-Footprint-1 5122.03,2636.55 r0 top
TP15 "TP" TP-Footprint-1 3582.78,4440.32 r0 top
TP16 "TP" TP-Footprint-1 4459.55,2621.89 r0 top
TP17 "TP" TP-Footprint-1 4530,2620 r0 top
TP18 "TP" TP-Footprint-1 4614.71,2613.2 r0 top
TP19 "TP" TP-Footprint-1 4500,2505 r0 top
TP20 "TP" TP-Footprint-1 4577.82,3062.35 r0 top
TP21 "TP" TP-Footprint-1 4610,2970 r0 top
TP22 "TP" TP-Footprint-1 4417.69,3712.34 r0 top
TP23 "TP" TP-Footprint-1 5029.17,2794.7 r0 top
TP24 "TP" TP-Footprint-1 4347.8,3712.34 r0 top
TP25 "TP" TP-Footprint-1 3308.43,2048.34 r90 top
TP26 "TP" TP-Footprint-1 3265.86,2110.47 r90 top
TP27 "TP" TP-Footprint-1 3123.9,2175.57 r0 top
TP28 "TP" TP-Footprint-1 2860.47,2045.74 r0 top
TP29 "TP" TP-Footprint-1 4786.71,4829.31 r0 top
TP30 "TP" TP-Footprint-1 4922.34,4823.79 r0 top
TP31 "TP" TP-Footprint-1 5348.92,4126.41 r0 top
TP32 "TP" TP-Footprint-1 5105,4690 r0 top
TP33 "TP" TP-Footprint-1 2896.43,3905.73 r0 top
TP34 "TP" TP-Footprint-1 5165,4210 r0 top
TP35 "TP" TP-Footprint-1 5365,3530 r0 top
TP36 "TP" TP-Footprint-1 3712.18,4345.33 r0 top
TP37 "TP" TP-Footprint-1 3684.04,2764.7 r0 top
TP38 "TP" TP-Footprint-1 3640,4345 r0 top
TP39 "TP" TP-Footprint-1 4052.79,3829.84 r0 top
TP40 "TP" TP-Footprint-1 4553.75,3138.41 r90 top
TP41 "TP" TP-Footprint-1 3682.24,4838.19 r0 top
TVS3 "PESD5Z5.0,115" DIO_BAS716,115 4758.05,4779.09 r180 top
TVS4 "PESD5Z5.0,115" DIO_BAS716,115 4937.53,4766.34 r0 top
U1 "TLV76708DGNR" TLV76708DGNR-Footprint-1 5204.2,2241.16 r0 top
U2 "TLV76701DGNR" FP-DGN0008G-MFG 5207.75,2494.4 r0 top
U3 "BCM1370" BCM1370-Footprint-1 4125,2425 r180 bottom value=-
U4 "TLV76750DGNR" TLV76708DGNR-Footprint-1 3413.17,2555.97 r90 top
U5 "ESP32-S3-WROOM-1-N16R8" ESP32-S3-WROOM-1-N16R8-Footprint-1 4178.86,4296.14 r0 top
U6 "74AVC4T774GUX" 74AVC4T774GUX-Footprint-1 4562.27,2783.48 r90 top
U7 "EMC2101-ACZL-TR" EMC2101-ACZL-TR-Footprint-1 3018.71,2035.29 r180 top
U8 "TPS25730SRSMR" QFN40P400X400X100_HS-33N 5141.74,4284.46 r180 bottom value=-
U9 "LS2406ERQ23" LS2406ERQ23-Footprint-1 4851.71,4524.56 r270 bottom value=-
U10 "TPS546D24ARVFR" TPS546D24ARVFR-Footprint-1 3277.69,4108.25 r90 bottom
Y1 "OXLTDLJANF-25.000000" OXLTDLJANF-25.000000-Footprint-1 4532.45,2360 r90 top

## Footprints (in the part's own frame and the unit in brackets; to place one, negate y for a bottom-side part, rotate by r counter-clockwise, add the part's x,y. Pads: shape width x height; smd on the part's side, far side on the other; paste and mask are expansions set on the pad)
74AVC4T774GUX-Footprint-1 [mm]
  rrect50% 0.55x0.22 smd mask+0.025: 1(-0.736,0.555) 2(-0.74,0.135) 3(-0.751,-0.26) 4(-0.744,-0.666) 9(0.758,-0.666) 10(0.762,-0.26) 11(0.762,0.135) 12(0.762,0.555)
  rrect50% 0.22x0.55 smd mask+0.025: 5(-0.586,-1.221) 6(-0.18,-1.225) 7(0.214,-1.229) 8(0.624,-1.217) 13(0.616,1.081) 14(0.214,1.084) 15(-0.184,1.084) 16(-0.578,1.088)
  body extent -0.89,-1.35 0.91,1.25, height 0.46
593D107X9020E2TE3-Footprint-1 [mil]
  rect 99x89 smd paste+0 mask+2: 1(-1.19,113.65) 2(-1.19,-108.35)
  body extent -90,-147 92,152, height 170
76341-304LF-Footprint-1 [mil]
  round 54 / inner round 60 / far side round 54 hole 34 paste-99999 mask+0: 1(-128.41,23.05) 2(-28.41,23.05) 3(71.59,23.05) 4(171.59,23.05)
  body extent -178,-27 222,73, height 276
BCM1370-Footprint-1 [mm]
  rrect50% 0.792x0.225 smd paste+0 mask+0.051: 1(-3.916,3.5) 2(-3.916,3) 3(-3.916,2.5) 4(-3.916,2) 5(-3.916,1.5) 6(-3.916,1) 7(-3.916,0.5) 8(-3.916,0) 9(-3.916,-0.5) 10(-3.916,-1) 11(-3.916,-1.5) 12(-3.916,-2) 13(-3.916,-2.5) 14(-3.916,-3) 15(-3.916,-3.5) 16(3.916,-3.5) 17(3.916,-3) 18(3.916,-2.5) 19(3.916,-2) 20(3.916,-1.5) 21(3.916,-1) 22(3.916,-0.5) 23(3.916,0) 24(3.916,0.5) 25(3.916,1) 26(3.916,1.5) 27(3.916,2) 28(3.916,2.5) 29(3.916,3) 30(3.916,3.5)
  rect 6.33x2 smd paste+0 mask+0.051: 31(0.006,2.876)
  rect 6.33x5.33 smd paste+0 mask+0.051: 32(0.008,-1.228)
CAPC1005X55X25LL05T10 [mm] "Chip Capacitor, 2-Leads, Body 1.00x0.50mm, IPC High Density"
  rect 0.56x0.52 smd paste+0 mask+0.051: 1(-0.39,0) 2(0.39,0)
  body extent -0.53,-0.28 0.53,0.28, height 0.55
DIO_BAS716,115 [mm]
  rect 0.5x0.6 smd paste-0.05 mask+0.051: 1(-0.7,0) 2(0.7,0)
  body extent -0.8,-0.4 0.8,0.4, height 0.65
EEF-SX0J181ER-Footprint-1 [mm]
  rect 2.4x2.8 smd paste+0 mask+0.051: 1(-3.137,0.031) 2(3.263,0.031)
  body extent -3.64,-2.11 3.76,2.19, height 1.9
EMC2101-ACZL-TR-Footprint-1 [mil]
  rect 60x18 smd paste+0 mask+2: 1(-81.31,39.9) 2(-81.31,14.31) 3(-81.31,-11.28) 4(-81.31,-36.88) 5(79.69,-36.88) 6(79.69,-11.28) 7(79.69,14.31) 8(79.69,39.9)
  body extent -97,-58 96,61, height 43
ESP32-S3-WROOM-1-N16R8-Footprint-1 [mil]
  rect 59x35 smd paste+0 mask+2: 1(-344.49,302.09) 2(-344.49,252.09) 3(-344.49,202.09) 4(-344.49,152.09) 5(-344.49,102.09) 6(-344.49,52.09) 7(-344.49,2.09) 8(-344.49,-47.91) 9(-344.49,-97.91) 10(-344.49,-147.91) 11(-344.49,-197.91) 12(-344.49,-247.91) 13(-344.49,-297.91) 14(-344.49,-347.91) 27(344.49,-347.91) 28(344.49,-297.91) 29(344.49,-247.91) 30(344.49,-197.91) 31(344.49,-147.91) 32(344.49,-97.91) 33(344.49,-47.91) 34(344.49,2.09) 35(344.49,52.09) 36(344.49,102.09) 37(344.49,152.09) 38(344.49,202.09) 39(344.49,252.09) 40(344.49,302.09)
  rect 35x59 smd paste+0 mask+2: 15(-275,-397.13) 16(-225,-397.13) 17(-175,-397.13) 18(-125,-397.13) 19(-75,-397.13) 20(-25,-397.13) 21(25,-397.13) 22(75,-397.13) 23(125,-397.13) 24(175,-397.13) 25(225,-397.13) 26(275,-397.13)
  rect 35x35 smd paste+0 mask+2: 41(-59.06,-1.85) 42(-114.17,53.27) 43(-114.17,-1.85) 44(-114.17,-56.97) 45(-59.06,-56.97) 46(-3.94,-56.97) 47(-3.94,-1.85) 48(-3.94,53.27) 49(-59.06,53.27)
  Top Layer keep-out region: 354.5,597 -354.5,597 -354.5,361 354.5,361
  body extent -354,-407 355,597, height 128
FID1X2R#1 [mm] "Fiducial - Round 1x2mm"
  round 2 smd paste-0.5 mask+0.051: 0(0,0)
FID1X2R#2 [mm] "Fiducial - Round 1x2mm"
  round 2 smd paste-0.5 mask+0.5: 0(0,0)
FP-0402-L_1_0_0_05-W_0_5-MFG#1 [mm]
  rect 0.45x0.5 smd paste+0 mask+0.051: 1(-0.475,0) 2(0.475,0)
  body extent -0.8,-0.38 0.8,0.38, height 0.25
FP-0402-L_1_0_0_05-W_0_5-MFG#2 [mm]
  rect 0.45x0.5 smd paste+0 mask+0: 1(-0.475,0) 2(0.475,0)
  body extent -0.8,-0.38 0.8,0.38, height 0.25
FP-0402-L_1_0_1-W_0_5_0_1-IPC_C [mil]
  rect 22.88x20.16 smd mask+1: 1(-14.39,0) 2(14.39,0)
  body extent -30,-16 30,16, height 10
FP-470531000-MFG [mm]
  rect 1.57x1.57 hole 1.02 paste-2539.97 mask+0: 1(3.81,-0.38)
  round 1.57 hole 1.02 paste-2539.97 mask+0: 2(1.27,-0.38) 3(-1.27,-0.38) 4(-3.81,-0.38)
  round 1.25 hole 1.25 unplated paste-2539.97 mask+0: ""(-1.27,-2.54)
  body extent -5.1,-2.92 5.1,2.92, height 10
FP-C0402-BB-MFG [mm]
  rect 0.52x0.52 smd paste+0 mask+0.051: 1(-0.4,0) 2(0.4,0)
  body extent -0.5,-0.25 0.5,0.25, height 0.55
FP-C2012-125-0_2-MFG [mm]
  rect 0.8x1.05 smd paste+0 mask+0.051: 1(-0.925,0) 2(0.925,0)
  body extent -1.43,-0.82 1.43,0.82, height 0.25
FP-C3216-160-0_2-MFG [mm]
  rect 1.1x1.35 smd paste+0 mask+0.051: 1(-1.65,0) 2(1.65,0)
  body extent -1.6,-0.8 1.6,0.8, height 1.8
FP-CC0402-IPC_B [mil]
  rect 22.37x22.54 smd paste+0 mask+2: 1(-17.8,0) 2(17.8,0)
  body extent -35,-17 35,17, height 10
FP-CC0402-IPC_C [mil]
  rect 18.43x18.6 smd paste+0 mask+2: 1(-15.83,0) 2(15.83,0)
  body extent -29,-15 29,15, height 10
FP-CC0402-MFG [mm]
  rect 0.5x0.5 smd paste+0 mask+0.051: 1(-0.5,0) 2(0.5,0)
  body extent -0.5,-0.25 0.5,0.25, height 0.55
FP-CC0805-0_85-MFG [mm]
  rect 0.95x1.4 smd paste+0 mask+0.051: 1(-0.925,0) 2(0.925,0)
  body extent -1.6,-1.05 1.6,1.05, height 0.25
FP-DGN0008G-MFG [mm]
  rrect22% 1.4x0.45 smd paste+0 mask+0.051: 1(-2.2,0.975) 2(-2.2,0.325) 3(-2.2,-0.325) 4(-2.2,-0.975) 5(2.2,-0.975) 6(2.2,-0.325) 7(2.2,0.325) 8(2.2,0.975)
  rrect5% 2x3 smd paste-1000 mask+0.051: 9(0,0)
  body extent -3,-1.8 3,1.8, height 0.25
FP-ERA2A-MFG [mm]
  rect 0.475x0.5 smd paste+0 mask+0.051: 1(-0.512,0) 2(0.512,0)
  body extent -0.85,-0.4 0.85,0.4, height 0.25
FP-GCM188-0_1-IPC_B [mil]
  rect 37.74x35.91 smd paste+0 mask+2: 1(-28.61,0) 2(28.61,0)
  body extent -31,-16 31,16, height 35
FP-GRM15-MFG [mm]
  rect 0.4x0.5 smd paste+0 mask+0.051: 1(-0.4,0) 2(0.4,0)
  body extent -0.7,-0.38 0.7,0.38, height 0.25
FP-GRM21B-0_2-e0_2_0_7-MFG [mm]
  rect 0.7x1.3 smd paste+0 mask+0.051: 1(-0.95,0) 2(0.95,0)
  body extent -1,-0.63 1,0.63, height 1.45
FP-GRM21B-0_15-IPC_A [mil]
  rect 55.34x59.38 smd paste+0 mask+2: 1(-36.47,0) 2(36.47,0)
  body extent -39,-25 39,25, height 55
FP-GRM21B-0_15-MFG [mm]
  rect 0.7x1.3 smd paste+0 mask+0.051: 1(-0.95,0) 2(0.95,0)
  body extent -1.4,-0.8 1.4,0.8, height 0.25
FP-GRM31C-0_3-e0_3_0_8-IPC_A [mil]
  rect 65.1x78.9 smd paste+0 mask+2: 1(-58.09,0) 2(58.09,0)
  body extent -110,-59 110,59, height 10
FP-GRM31C-0_3-e0_3_0_8-MFG [mm]
  rect 1.15x1.8 smd paste+0 mask+0.051: 1(-1.575,0) 2(1.575,0)
  body extent -1.6,-0.8 1.6,0.8, height 1.9
FP-GRM155-0_2-MFG [mm]
  rect 0.45x0.6 smd paste+0 mask+0.051: 1(-0.475,0) 2(0.475,0)
  body extent -0.5,-0.25 0.5,0.25, height 0.7
FP-GRM155-0_05-IPC_B [mil]
  rect 24.23x22.54 smd paste+0 mask+2: 1(-16.87,0) 2(16.87,0)
  body extent -20,-10 20,10, height 22
FP-GRM155-0_05-MFG [mm]
  rect 0.4x0.5 smd paste+0 mask+0.051: 1(-0.4,0) 2(0.4,0)
  body extent -0.5,-0.25 0.5,0.25, height 0.55
FP-GRM155-0_15-IPC_C [mil]
  rect 23.78x21.98 smd mask+1: 1(-14.85,0) 2(14.84,0)
  body extent -20,-10 20,10, height 26
FP-LB_Q39E-MFG [mm]
  rect 0.8x0.8 smd paste+0 mask+0.051: 1(-0.75,0) 2(0.75,0)
  body extent -1.25,-0.55 1.25,0.55, height 0.25
FP-RK73H2A-MFG [mm]
  rect 0.6x1.05 smd paste+0 mask+0.051: 1(-0.95,0) 2(0.95,0)
  body extent -1,-0.63 1,0.63, height 0.6
FP-RK73H2E-MFG [mm]
  rect 0.9x2.3 smd paste+0 mask+0.051: 1(-1.55,0) 2(1.55,0)
  body extent -1.6,-1.3 1.6,1.3, height 0.7
FP-RK73Z1E-IPC_B [mil]
  rect 23.14x22.54 smd paste+0 mask+2: 1(-18.27,0) 2(18.27,0)
  body extent -36,-17 36,17, height 10
FP-SOD123W-MFG [mm]
  rect 1.2x1.2 smd paste-1000 mask+0.051: 1(-1.4,0) 2(1.4,0)
  body extent -1.75,-0.85 1.75,0.85, height 1.1
FP-SP4024-CA-MFG [mm]
  rect 0.49x0.45 smd paste+0 mask+0.051: 1(-1.14,0) 2(1.14,0)
  body extent -1.3,-0.65 1.3,0.65, height 1
FP-VLMO1500-GS08-MFG [mm]
  rect 0.6x0.7 smd paste+0 mask+0.051: 1(-0.475,0) 2(0.475,0)
  body extent -0.87,-0.45 0.87,0.45, height 0.25
GCT_USB4145-03-0170-C_REVA2 [mm]
  rect 0.3x1.15 smd paste+0 mask+0.051: A1(-2.75,1.485) A4(-1.25,1.485) A5(-0.75,1.485) A6(-0.25,1.485) A7(0.25,1.485) A8(0.75,1.485) A9(1.25,1.485) A12(2.75,1.485) B1(2.75,-1.485) B4(1.25,-1.485) B5(0.75,-1.485) B6(0.25,-1.485) B7(-0.25,-1.485) B8(-0.75,-1.485) B9(-1.25,-1.485) B12(-2.75,-1.485)
  oval 1.6x1.1 hole 0.6 slot 1.1 at 0 deg: S1(-4,1.43) S2(4,1.43) S3(-4,-1.43) S4(4,-1.43)
  round 0.71 hole 0.71 unplated: ""(-4,0) ""(4,0)
  body extent -4.5,-1.84 4.44,1.85, height 7.46
LS2406ERQ23-Footprint-1 [mil]
  rect 32x10 smd paste+0 mask+2: 1(-50.87,49.09) 2(-50.87,25.46) 3(-50.88,1.84) 4(-50.88,-21.78) 5(-50.88,-45.4) 9(51.12,-45.4) 10(51.12,-21.78) 11(51.12,1.84) 12(51.13,25.46) 13(51.13,49.09)
  rect 7x51 smd paste+0 mask+2: 6(-23.5,-53.66) 7(0.12,-53.66) 8(23.74,-53.66) 14(23.74,57.34) 15(0.13,57.34) 16(-23.5,57.34)
  body extent -51,-63 51,67, height 31
MP4570GF-Z-Footprint-1 [mm]
  rect 1.475x0.45 smd paste+0 mask+0.051: 1(-2.938,2.925) 2(-2.938,2.275) 3(-2.938,1.625) 4(-2.938,0.975) 5(-2.938,0.325) 6(-2.938,-0.325) 7(-2.938,-0.975) 8(-2.938,-1.625) 9(-2.938,-2.275) 10(-2.938,-2.925) 11(2.938,-2.925) 12(2.938,-2.275) 13(2.938,-1.625) 14(2.938,-0.975) 15(2.938,-0.325) 16(2.938,0.325) 17(2.938,0.975) 18(2.938,1.625) 19(2.938,2.275) 20(2.938,2.925)
  rect 3.1x4.3 smd paste+0 mask+0.051: 21(0,0)
  body extent -3.2,-3.25 3.2,3.25, height 1.2
"New footprint 1" [mm]
  rrect50% 1.3x0.4 smd paste+0 mask+0.051: 1(0,1.95) 2(0,1.3) 3(0,0.65) 4(0,0)
  round 0.025 smd paste+0 mask+0.051: 5(2.171,0.027) 7(2.171,1.927)
  Top Layer region: 1.064,1.121 1.064,2.733 1.064,2.734 1.364,2.734 1.364,2.534 2.824,2.534 2.824,2.184 3.274,2.184 3.274,1.761 2.814,1.761 2.812,1.759 2.812,1.544 3.277,1.544 3.277,1.121
  Top Layer region: 1.064,0.834 1.064,-0.778 1.065,-0.779 1.365,-0.779 1.365,-0.579 2.825,-0.579 2.825,-0.229 3.275,-0.229 3.275,0.194 2.814,0.194 2.812,0.196 2.812,0.411 3.278,0.411 3.278,0.834
  body extent -0.2,-0.7 3.1,2.6, height 1.12
OXLTDLJANF-25.000000-Footprint-1 [mm]
  rrect50% 1.2x1.1 smd paste+0 mask+0.051: 1(0,0) 2(2.1,0) 3(2.1,1.6) 4(0,1.6)
QFN40P400X400X100_HS-33N [mm] "QFN, 32-Leads, Body 4.00x4.00mm, Pitch 0.40mm, Thermal Pad 2.83x2.80mm, IPC Medium Density"
  oval 0.75x0.2 smd paste+0 mask+0.051: 1(-2,1.4) 2(-2,1) 3(-2,0.6) 4(-2,0.2) 5(-2,-0.2) 6(-2,-0.6) 7(-2,-1) 8(-2,-1.4) 17(2,-1.4) 18(2,-1) 19(2,-0.6) 20(2,-0.2) 21(2,0.2) 22(2,0.6) 23(2,1) 24(2,1.4)
  oval 0.2x0.75 smd paste+0 mask+0.051: 9(-1.4,-2) 10(-1,-2) 11(-0.6,-2) 12(-0.2,-2) 13(0.2,-2) 14(0.6,-2) 15(1,-2) 16(1.4,-2) 25(1.4,2) 26(1,2) 27(0.6,2) 28(0.2,2) 29(-0.2,2) 30(-0.6,2) 31(-1,2) 32(-1.4,2)
  rect 2.83x2.8 smd paste+0 mask+0.051: 33(0,0)
  body extent -1.99,-2.01 2.01,1.99, height 1
RESC1005X40X25LL10T10 [mm] "Chip Resistor, 2-Leads, Body 1.00x0.50mm, IPC High Density"
  rect 0.55x0.5 smd paste+0 mask+0.051: 1(-0.375,0) 2(0.375,0)
  body extent -0.55,-0.3 0.55,0.3, height 0.4
RESC1005X40X25ML10T10 [mm] "Chip Resistor, 2-Leads, Body 1.00x0.50mm, IPC Low Density"
  rect 0.75x0.7 smd paste+0 mask+0.051: 1(-0.475,0) 2(0.475,0)
  body extent -0.55,-0.3 0.55,0.3, height 0.4
RESC1005X40X25NL10T10 [mm] "Chip Resistor, 2-Leads, Body 1.00x0.50mm, IPC Medium Density"
  rect 0.65x0.6 smd paste+0 mask+0.051: 1(-0.425,0) 2(0.425,0)
  body extent -0.55,-0.3 0.55,0.3, height 0.4
RK73H1ETTP2201F-Footprint-1 [mm]
  rect 0.598x0.6 smd paste+0 mask+0.051: 1(-0.55,0) 2(0.55,0)
  body extent -0.54,-0.21 0.48,0.29, height 0.4
ROHM-SOT723-3_V [mm] "SOT723, 3-Leads, Body 1.2x0.8mm, Pitch 0.8mm"
  rrect30% 0.45x0.4 smd paste+0 mask+0.051: 1(-0.575,0.4) 2(-0.575,-0.4)
  rrect30% 0.45x0.5 smd paste+0 mask+0.051: 3(0.575,0)
  body extent -0.53,-0.63 0.53,0.63, height 0.45
SHORT06-FP [mm]
  rect 0.6x0.6 smd paste-0.4 mask+0.051: 1(-0.4,0) 2(0.4,0)
  Top Layer region: -0.2,0.3 -0.2,-0.3 0.2,-0.3 0.2,0.3
SRP1265A-R33M [mm] "330 nH Shielded Drum Core, Wirewound Inductor 46 A 0.8mOhm Max Nonstandard"
  rect 3.1x5 smd paste+0 mask+0.051: 1(-5.55,-0.127) 2(5.55,-0.127)
  body extent -6.43,-6.4 6.47,6.1, height 6.33
SRP5020TA-6R8M-Footprint-1 [mm]
  rect 2x2.8 smd paste+0 mask+0.051: 1(-2.099,0.069) 2(2.101,0.069)
  body extent -2.74,-2.56 2.96,2.64, height 1.81
SW_B3SL-1002P_OMR [mm]
  rect 2.75x1 smd paste+0 mask+0.051: 1(-2.875,2) 2(2.875,2) 3(-2.875,-2) 4(2.875,-2)
  body extent -3.48,-3.25 3.52,3.25, height 3.4
TLV76708DGNR-Footprint-1 [mm]
  rrect22% 1.4x0.45 smd paste+0 mask+0.051: 1(-2.236,1.017) 2(-2.236,0.367) 3(-2.236,-0.283) 4(-2.236,-0.933) 5(2.164,-0.933) 6(2.164,-0.283) 7(2.164,0.367) 8(2.164,1.017)
  rrect5% 2x3 smd paste-1000 mask+0.051: 9(-0.036,0.042)
  body extent -3.04,-1.76 2.96,1.84, height 0.25
TP-Footprint-1 [mm]
  round 1.2 smd paste+0 mask+0.051: 1(0,0)
TPS546D24ARVFR-Footprint-1 [mm]
  rect 0.6x0.25 smd paste+0 mask+0.051: 1(-2.469,2.768) 2(-2.469,2.268) 3(-2.469,1.768) 4(-2.469,1.268) 5(-2.469,0.768) 6(-2.469,0.268) 7(-2.469,-0.232) 8(-2.469,-0.732) 9(-2.469,-1.232) 10(-2.469,-1.732) 11(-2.469,-2.232) 12(-2.469,-2.732) 21(2.331,-2.732) 22(2.331,-2.232) 23(2.331,-1.732) 24(2.331,-1.232) 25(2.331,-0.732) 26(2.331,-0.232) 27(2.331,0.268) 28(2.331,0.768) 29(2.331,1.268) 30(2.331,1.768) 31(2.331,2.268) 32(2.331,2.768)
  rect 0.25x0.6 smd paste+0 mask+0.051: 13(-1.819,-3.382) 14(-1.319,-3.382) 15(-0.819,-3.382) 16(-0.319,-3.382) 17(0.181,-3.382) 18(0.681,-3.382) 19(1.181,-3.382) 20(1.681,-3.382) 33(1.681,3.418) 34(1.181,3.418) 35(0.681,3.418) 36(0.181,3.418) 37(-0.319,3.418) 38(-0.819,3.418) 39(-1.319,3.418) 40(-1.819,3.418)
  rect 3.3x5.3 smd paste-2.637 mask+0.051: 41(-0.069,0.018)
  body extent -2.58,-3.47 2.42,3.53, height 1.52
VISH-7343-31_N [mm] "Molded Capacitor, 2-Leads, Body 7.6x4.6mm, IPC Medium Density"
  rect 2.55x2.45 smd paste+0 mask+0.051: 1(-3.025,0) 2(3.025,0)
  body extent -4.02,-2.3 4.02,2.3, height 3.1

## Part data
C1 C2 C3 C4 C11 C12 C23 C24 C26 C43 C55 C76: library part CMP-x00152-1, "Ceramic Capacitor, Multilayer, Ceramic, 50V, 10% +Tol, 10% -Tol, X7R, 15% TC, 0.1uF, Surface Mount, 0402"
C5 C66: library part CMP-x00143-1, "Ceramic Capacitor, Multilayer, Ceramic, 50V, 10% +Tol, 10% -Tol, X7R, 15% TC, 0.001uF, Surface Mount, 0805"
C6 C7 C8 C9 C13 C14 C15 C82 C83 C84 C85 C86: library part CMP-x00039-4, "Ceramic Capacitor, Multilayer, Ceramic, 16V, 10% +Tol, 10% -Tol, X5R, 15% TC, 1uF, Surface Mount, 0402", Manufacturer="Taiyo Yuden", Package=0402, Rating=16V, Template=TY_0402
C10 C17 C19 C20 C21 C45 C49: library part CMP-001-00094-1, "Multilayer Ceramic Capacitor, 0.1 uF, 25 V, ± 10%, X7R, 0402 [1005 Metric]", Package=0402, Rating=16V
C16: library part CMP-001-00145-3, "Ceramic Capacitor, Multilayer, Ceramic, 25V, 10% +Tol, 10% -Tol, X5R, 15% TC, 10uF, Surface Mount, 0805", Manufacturer=Murata, Package=0805, Rating=25V, Template=MR_0805
C18: library part CMP-001-00203-2, "Ceramic Capacitor, Multilayer, Ceramic, 16V, 10% +Tol, 10% -Tol, X7R, 15% TC, 0.1uF, Surface Mount, 0402", Case/Package=0402, Manufacturer=Murata, Rating=16V, Template=MR_0402
C22: library part CMP-001-00097-1, "CAPACITOR - Ceramic Chip Cap, 0402, 470 pf, 10%, 50V, X7R", Package=0402, Rating=50V
C25: library part CMP-001-00022-7, "Solid Tantalum Chip Capacitor, 47 uF, +/- 10%, 16 V, -55 to 125 degC, 2917 (7343 Metric), RoHS, Tape and Reel", Capacitor Type=Tantalum, Case/Package=7343-31, Manufacturer="Vishay Semiconductor", Max Operating Temperature=125°C, Min Operating Temperature=-55°C, Package Description="2-Pin Surface Mount Device, Body 7.3 x 4.3 mm", Tolerance=10%, Voltage Rating=16V
C27 C28 C73 C74 C75: library part CMP-x00157-1, "Ceramic Capacitor, Multilayer, Ceramic, 10V, 10% +Tol, 10% -Tol, X7R, 15% TC, 10uF, Surface Mount, 0805"
C29 C30 C67 C78: library part CMP-03422-000489-1, "CAP CER 1UF 10V X5R 0402", Capacitance="1 uF", Manufacturer=YAGEO, Package=CC0402, Temperature="-55°C to +125°C", Temperature Characteristic=X5R, Temperature Coefficient=30ppm/°C, Temperature Range High=+125°C, Temperature Range Low=-55°C, Tolerance=0.1, Voltage Rating="10 V"
C31: library part CMP-2008-04169-1, Manufacturer=Murata
C32 C33: library part CMP-2008-04581-2, "Chip Multilayer Ceramic Capacitors for General Purpose, 0402, 1.0uF, X5R, 15%, 10%, 25V", Capacitance=1uF, Case Code (Imperial)=0402, Case Code (Metric)=1005, Dielectric=X5R, Max Operating Temperature=85°C, Min Operating Temperature=-55°C, Package Quantity=10000, Tolerance=10%, Voltage=25V
C34 C35 C36: library part CMP-08246-006023-1, "Multilayer Ceramic Capacitors 3.3μF ±10% 25V X7R SMD 0805", Case Code (Imperial)=0805, Case Code (Metric)=2012, Dielectric=X7R, Dielectric Material=Ceramic, Max Operating Temperature=125°C, Min Operating Temperature=-55°C, Package Quantity=1, Tolerance=10%, Voltage Rating=25V
C37: library part CMP-2008-04366-1, Manufacturer=Murata
C38: library part CMP-06035-016894-1, "Chip Multilayer Ceramic Capacitors for General Purpose, 0402, 8200pF, C0G, 30ppm/°C, 5%, 50V"
C39 C40 C52: library part CMP-x00115-1, "Ceramic Capacitor, Multilayer, Ceramic, 50V, 10% +Tol, 10% -Tol, X7R, 15% TC, 0.022uF, Surface Mount, 0402", Manufacturer=Murata, Package=0402, Template=MR_0402
C41: library part CMP-x00092-1, "Ceramic Capacitor, Multilayer, Ceramic, 25V, 10% +Tol, 10% -Tol, X7R, 15% TC, 1uF, Surface Mount, 0603", Manufacturer=Murata, Package=1608, Template=MR_1608
C42 C44 C48: library part CMP-x00183-1, "Ceramic Capacitor, Multilayer, Ceramic, 10V, 20% +Tol, 20% -Tol, X5R, 15% TC, 10uF, Surface Mount, 0402"
C46 C47: library part CMP-x00111-1, "Ceramic Capacitor, Multilayer, Ceramic, 50V, 10% +Tol, 10% -Tol, X7R, 15% TC, 0.00033uF, Surface Mount, 0402", Manufacturer=Kemet, Package=0402, Template=KM_0402
C50 C51: library part CMP-001-00268-1, "Ceramic Capacitor, Multilayer, Ceramic, 50V, 10% +Tol, 10% -Tol, X5R, 15% TC, 4.7uF, Surface Mount, 0805", Capacitor Type=Ceramic, Case/Package=0805, Max Operating Temperature=85°C, Min Operating Temperature=-55°C
C53 C54 C60 C61 C62 C63: library part CMP-06035-043516-1, "Chip Multilayer Ceramic Capacitors for General Purpose, 1206, 22uF, X6S, 22%, 20%, 25V", Capacitance=22uF, Dielectric=X6S, Tolerance=20%, Voltage Rating (DC)=25V
C56 C57: library part CMP-x00156-1, "Ceramic Capacitor, Multilayer, Ceramic, 25V, 10% +Tol, 10% -Tol, X7R, 15% TC, 0.0022uF, Surface Mount, 0402"
C58 C59: library part CMP-001-00321-3, "No Description Available", Mfr_Name=Vishay
C64 C65: library part CMP-2000-05397-3, "Multilayer Ceramic Capacitors 47uF ±20% 25V X5R SMD 1206", Capacitance=47uF, Case Code (Imperial)=1206, Case Code (Metric)=3216, Dielectric=X5R, Dielectric Material=Ceramic, Max Operating Temperature=85°C, Min Operating Temperature=-55°C, Package Quantity=1, Tolerance=20%, Voltage=25V
C68 C69: library part CMP-x00146-3, "Cap Aluminum Polymer 180uF 6.3VDC 20%( 7.3 X 4.3 X 1.9mm) SMD 0.009 Ohm 6300mA 2000h 105C T/R", Manufacturer=Panasonic, Package=SMD-2, Template=PS_SMD2_C
C70 C71 C72 C79: library part CMP-x00148-1, "Ceramic Capacitor, Multilayer, Ceramic, 6.3V, 20% +Tol, 20% -Tol, X7R, 15% TC, 22uF, Surface Mount, 0805"
C77: library part CMP-x00153-1, "Ceramic Capacitor, Multilayer, Ceramic, 50V, 10% +Tol, 10% -Tol, X7R, 15% TC, 0.0001uF, Surface Mount, 0402"
C80 C81: library part CMP-x00203-1, "Ceramic Capacitor, Multilayer, Ceramic, 6.3V, 20% +Tol, 20% -Tol, X5R, 15% TC, 100uF, Surface Mount, 1206", Manufacturer=Murata, Package=1206, Template=MR_1206_C
D1: library part CMP-00030-24098164-1, "RED 0402 VLMx1500", Ambient Temperature Range High=85°C, Case Code (Imperial)=0402, Case Code (Metric)=1005, Color=Orange, Forward Current=20mA, Forward Voltage=2V, Min Operating Temperature=-30°C, Power Dissipation=75mW, Reverse Voltage=5V
D2: library part CMP-00030-24098164-1, "GREEN 0402 VLMx1500", Ambient Temperature Range High=85°C, Case Code (Imperial)=0402, Case Code (Metric)=1005, Color=Orange, Forward Current=20mA, Forward Voltage=2V, Min Operating Temperature=-30°C, Power Dissipation=75mW, Reverse Voltage=5V
D3: library part CMP-00030-24098164-1, "YELLOW 0402 VLMx1500", Ambient Temperature Range High=85°C, Case Code (Imperial)=0402, Case Code (Metric)=1005, Color=Orange, Forward Current=20mA, Forward Voltage=2V, Min Operating Temperature=-30°C, Power Dissipation=75mW, Reverse Voltage=5V
D4: library part CMP-x00114-1, "Trans Voltage Suppressor Diode, 350W, 24V V(RWM), Bidirectional, 1 Element, Silicon", Manufacturer=Littelfuse, Package=SOD_323_2, Template=LF_SOD_323
D5 D6: library part CMP-62016-000029-1, "LED BLUE DIFFUSED 0603 SMD", Case Code (Imperial)=0603, Case Code (Metric)=1608, Color=Blue, Forward Voltage=2.85V, Lens Color=White, Test Current=5mA
D7: library part CMP-x00083-1, "Rectifier Diode, Schottky, 1 Phase, 1 Element, 3A, 40V V(RRM), Silicon", Manufacturer=Nexperia, Package=SOD-123W-2, Template=NX_SOD_123W_2
FD1 FD2 FD3 FD4 FD5 FD6: library part CMP-00028-00005-4, "Fiducial - Round 1x2mm"
IC1: library part CMP-001-0077-1, "Switching Voltage Regulators 3A,4.5V-55V Input, Freqcy Programmable", Package=TSSOP-EP-20
J1: library part CMP-x00140-1
J2: library part CMP-04776-000290-2, "CONN HEADER VERT 4POS 2.54MM", Ambient Temperature Range High=105°C, Current Rating=500mA, Housing Color=Beige, Manufacturer Lifecycle Status=ACTIVE, Max Operating Temperature=75°C, Min Operating Temperature=0°C, Voltage Rating=250V
J4: library part CMP-349-000000-01-A-2, Package=None
L1: library part CMP-x00175-1, "General Purpose Inductor, 6.8uH, 20%, 1 Element, Metal Alloy Powder-Core, SMD, 2220"
L2: library part CMP-00047-01-A-1, "General Purpose Inductor, 0.33uH, 20%, 1 Element, Carbonyl Powder-Core, SMD, 5349", Case/Size Code=5349, DC Resistance (DCR)=0.8mR, Inductance-Nom (L)=0.33uH, Inductor Application="POWER INDUCTOR", Inductor Type="GENERAL PURPOSE INDUCTOR", Max Current Rating=46A, Max Operating Temperature=150°C, Min Operating Temperature=-40°C, Package Height=6.2mm, Package Length=13.5mm, Package Style=SMTMeter, Package Width=12.5mm, Self Resonant Frequency=90MHz, Test Frequency=100kHz, Tolerance=20%
Q1 Q2 Q3: library part CMP-013-00026-2, "Nch Small Signal MOSFET, 50 V, 200 mA, 3-Pin SOT723, RoHS, Tape and Reel"
Q4: library part CMP-x00106-2, "Power Field-Effect Transistor", Manufacturer=Vishay, Package=PP12-8, Template=VS_PP12_8
R1: library part CMP-x00159-1, "Fixed Resistor, Metal Glaze/thick Film, 0.1W, 51100ohm, 75V, 1% +/-Tol, 100ppm/Cel, Surface Mount, 0402"
R2: library part CMP-x00160-1, "Fixed Resistor, Metal Glaze/thick Film, 0.1W, 102000ohm, 75V, 1% +/-Tol, 100ppm/Cel, Surface Mount, 0402"
R3 R7 R8: library part CMP-x00163-1, "Fixed Resistor, Metal Glaze/thick Film, 0.1W, 1000ohm, 75V, 1% +/-Tol, 100ppm/Cel, Surface Mount, 0402"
